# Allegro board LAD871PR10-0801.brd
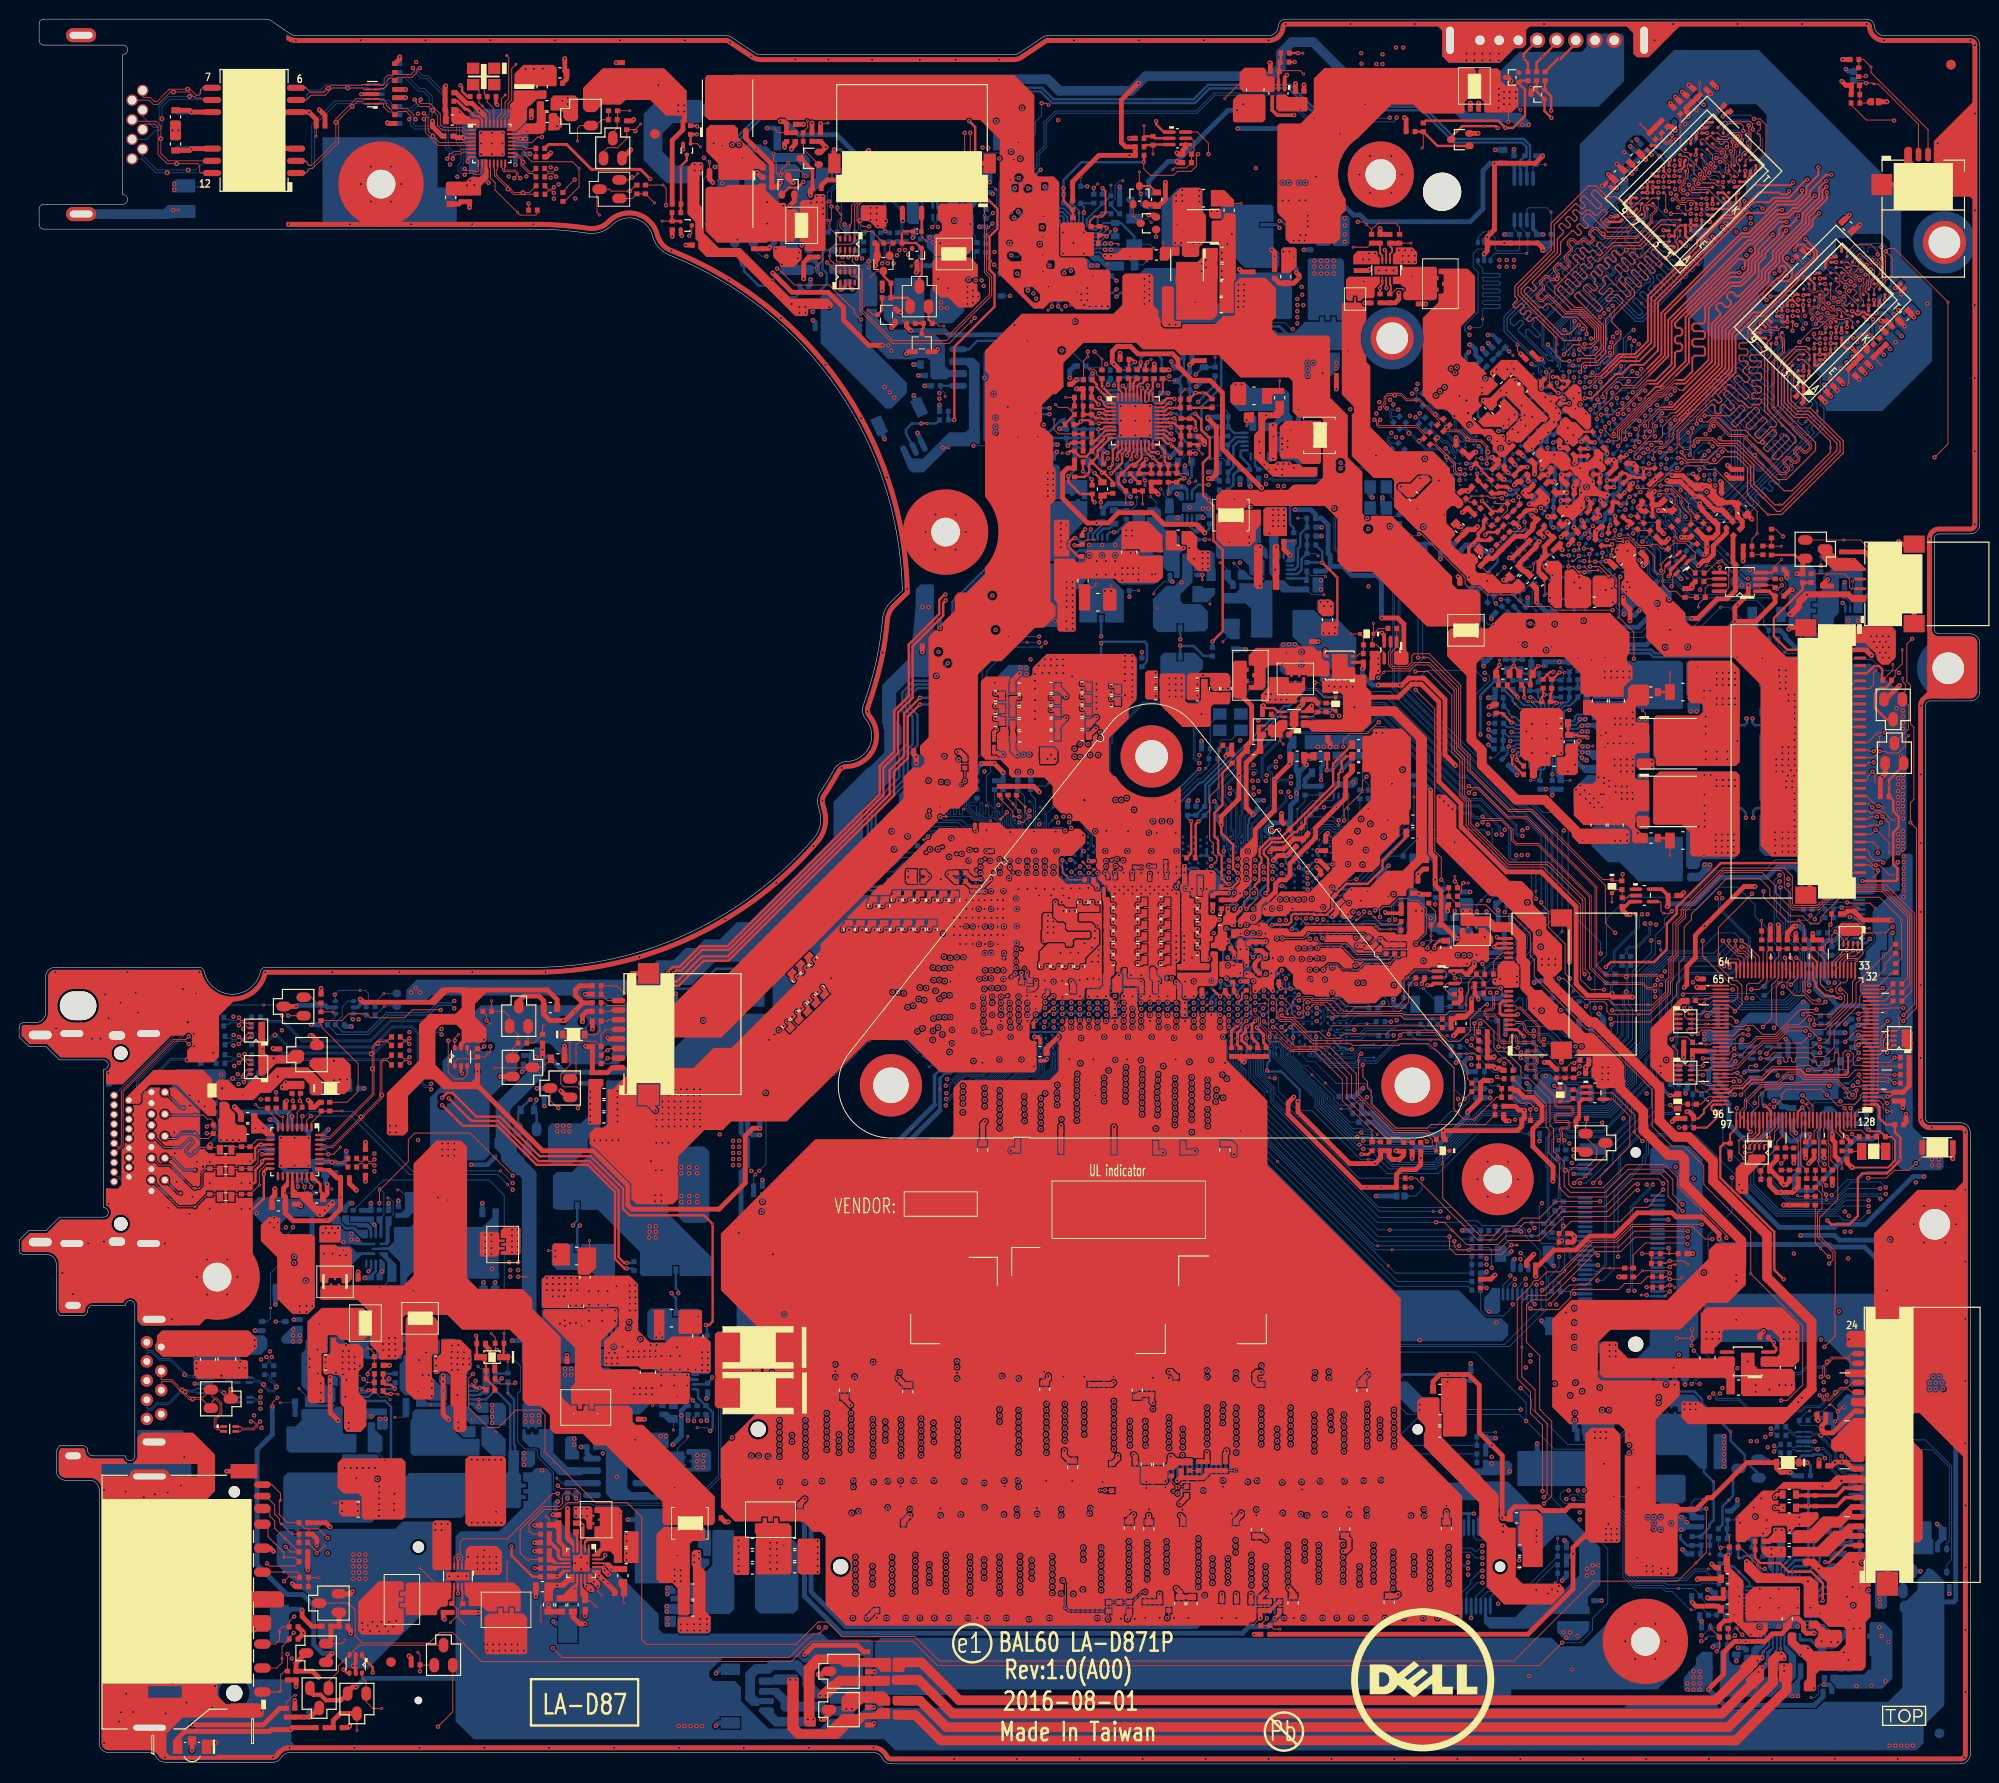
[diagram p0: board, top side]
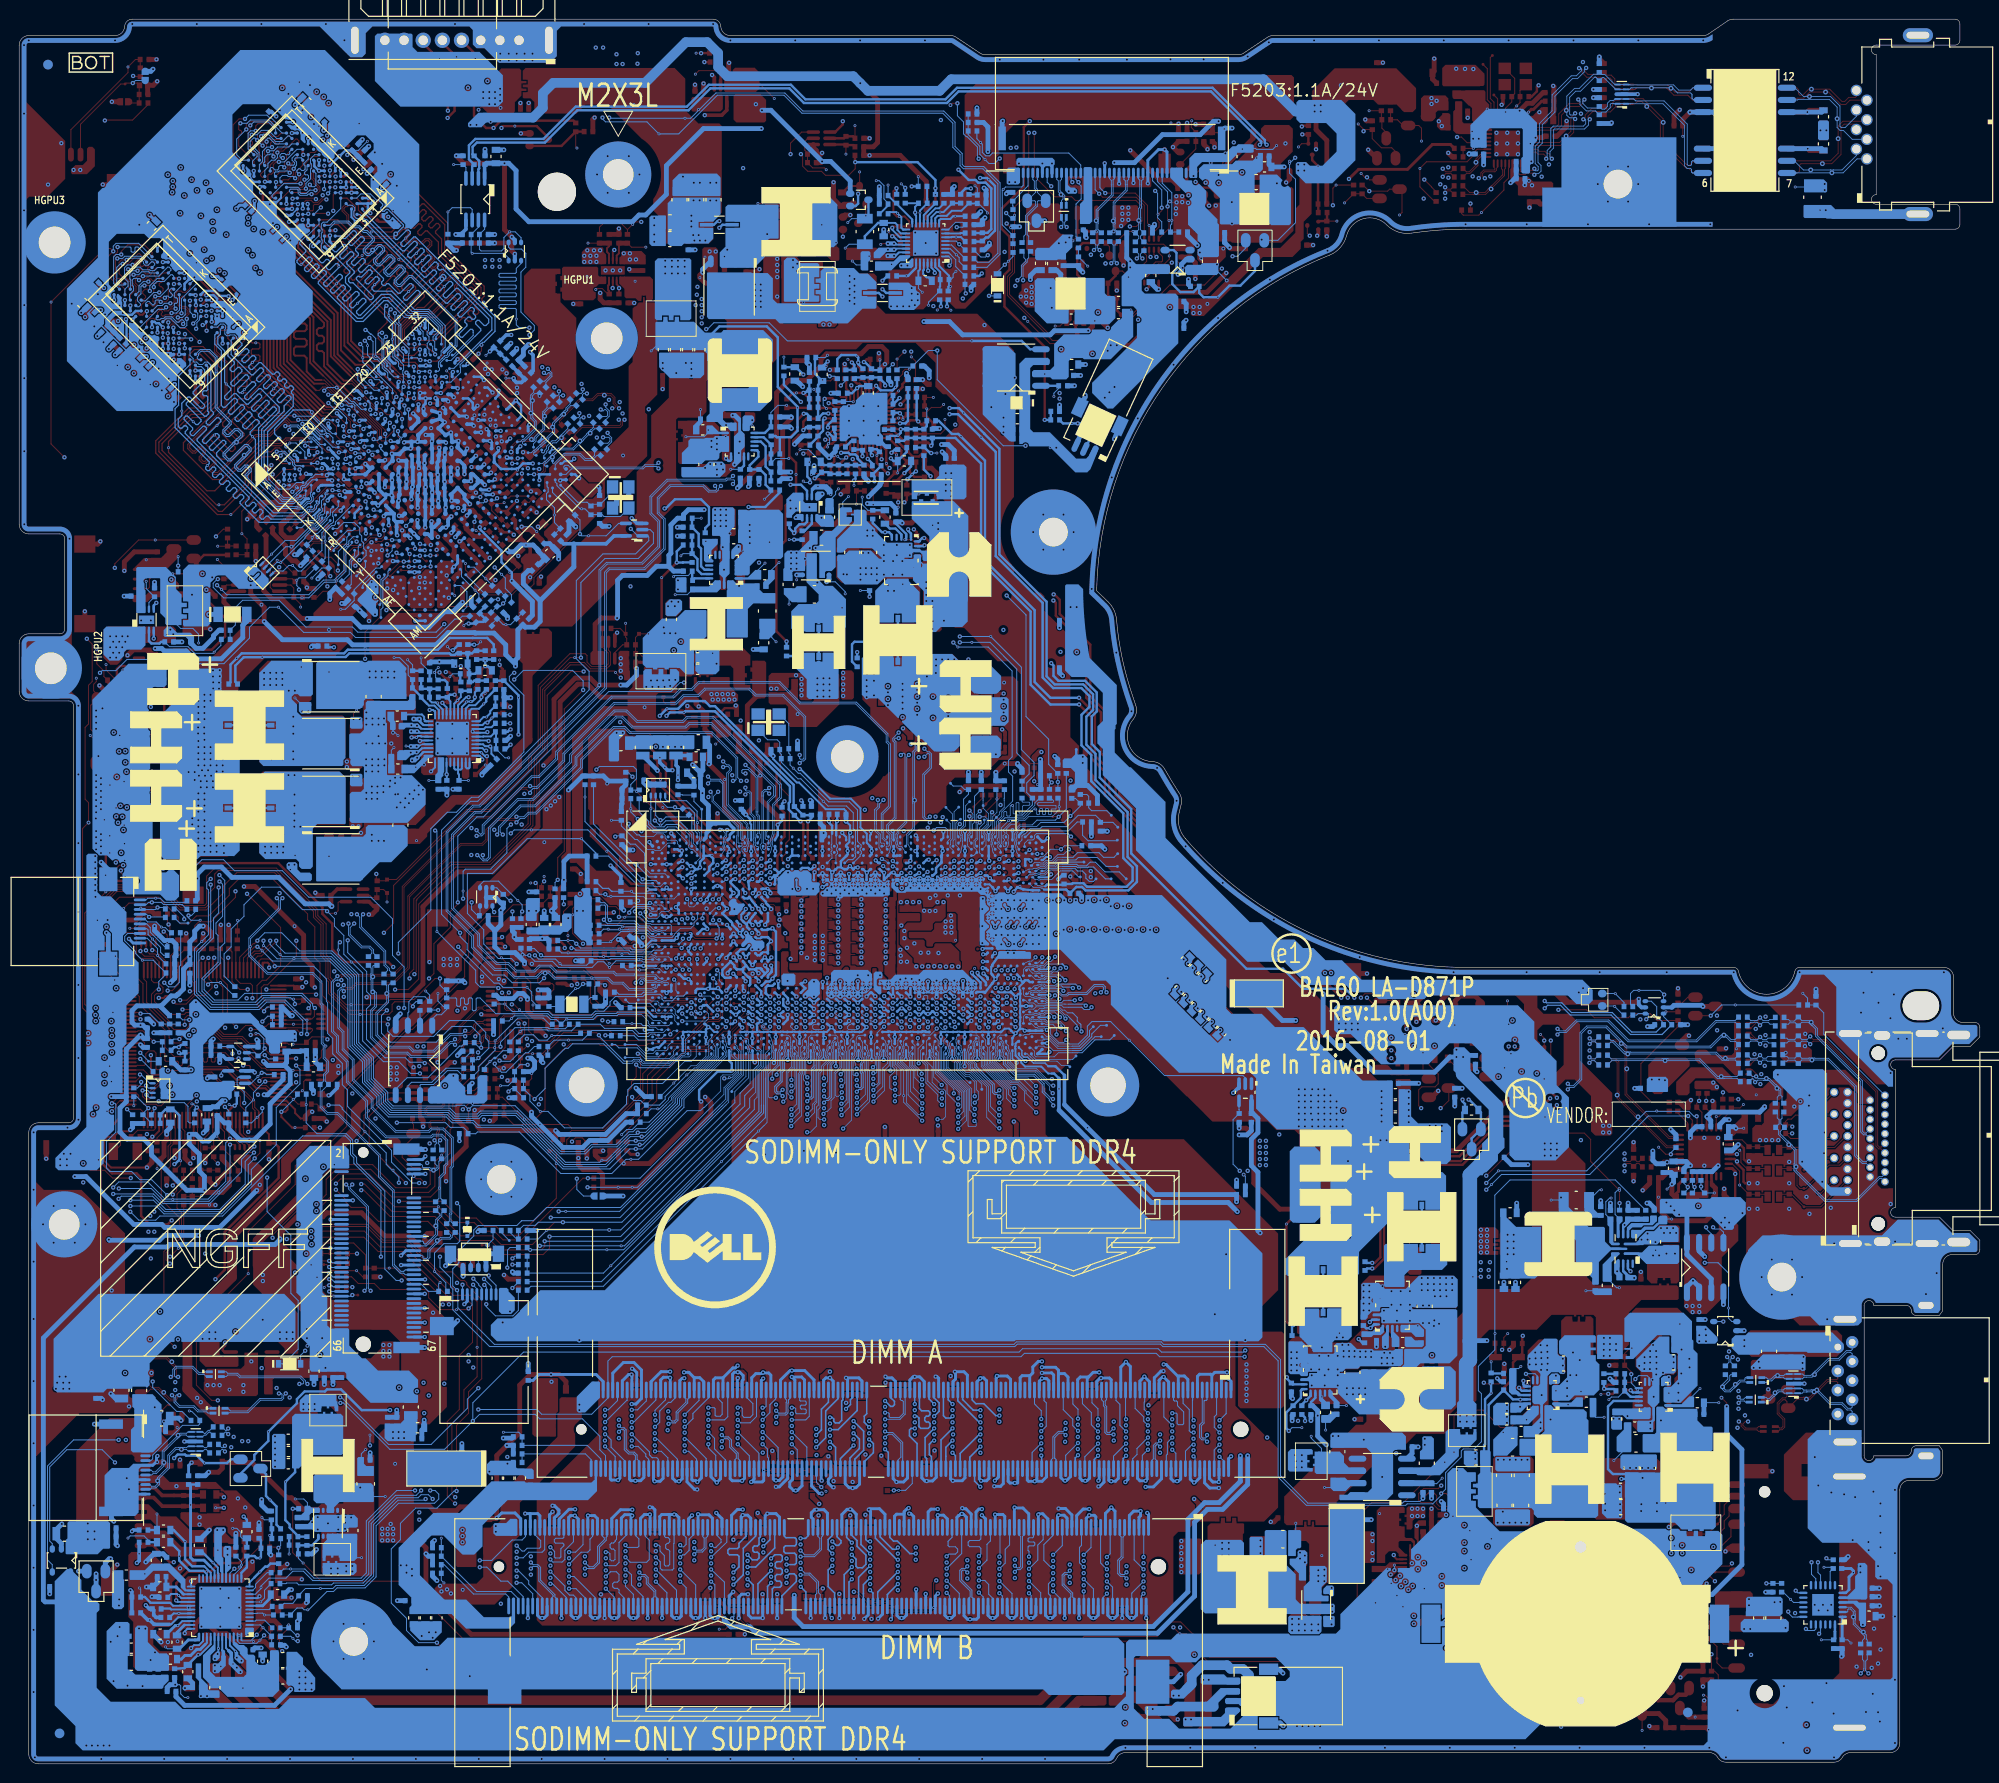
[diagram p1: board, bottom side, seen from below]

Outline 204.55 x 181.97 mm; copper layers: TOP, VCC, IN1, IN2, GND, BOTTOM. Coordinates in mm from the lower left corner of the outline.
Outline path: 0,76.82 0,75.82 1,74.82 2.8,74.82 4.2,73.42 8.8,73.42 arc(9.3,72.92) 8.8,72.42 8.8,58.02 arc(9.3,57.52) 8.8,57.02 4.2,57.02 2.8,55.62 1,55.62 0,54.62 0,53.62 arc(0.15,53.27) 0.5,53.12 2.87,53.12 arc(3.58,52.83) 3.87,52.12 3.87,47.27 4.22,46.77 6.65,46.77 arc(7,46.92) 7.15,47.27 arc(7.31,47.66) 7.7,47.82 11.07,47.82 arc(11.57,48.32) 12.07,47.82 12.07,32.12 arc(11.57,31.62) 11.07,32.12 7.7,32.12 arc(7.31,32.28) 7.15,32.67 arc(7,33.02) 6.65,33.17 4.22,33.17 3.87,32.67 3.87,30.57 arc(4.16,29.86) 4.87,29.57 7.35,29.57 arc(8.06,29.28) 8.35,28.57 8.35,2.17 arc(8.64,1.46) 9.35,1.17 13.48,1.17 arc(13.98,1.04) 14.35,0.67 arc(14.71,0.3) 15.21,0.17 26.49,0.17 arc(26.99,0.3) 27.35,0.67 arc(27.72,1.04) 28.22,1.17 89.14,1.17 arc(89.68,1.01) 90.05,0.58 arc(90.42,0.16) 90.96,0 202.55,0 arc(203.26,0.29) 203.55,1 203.55,65.86 arc(203.26,66.57) 202.55,66.86 199.38,66.86 arc(199.03,67.01) 198.88,67.36 198.88,110.36 arc(199.03,110.71) 199.38,110.86 203.55,110.86 arc(204.26,111.15) 204.55,111.86 204.55,116.86 arc(204.26,117.57) 203.55,117.86 200.3,117.86 arc(199.95,118.01) 199.8,118.36 199.8,127.78 arc(199.95,128.13) 200.3,128.28 203.55,128.28 arc(204.26,128.57) 204.55,129.28 204.55,179.26 arc(204.26,179.97) 203.55,180.26 194.55,180.26 arc(193.86,180.54) 193.55,181.21 arc(193.3,181.75) 192.75,181.97 132.15,181.97 arc(131.6,181.75) 131.35,181.21 arc(131.04,180.54) 130.35,180.26 107.35,180.26 arc(107.06,180.22) 106.8,180.09 104.3,178.43 arc(104.04,178.3) 103.75,178.26 77.35,178.26 arc(77.06,178.3) 76.8,178.43 74.3,180.09 arc(74.04,180.22) 73.75,180.26 28.86,180.26 arc(28.56,180.3) 28.29,180.43 26.31,181.8 arc(26.04,181.93) 25.74,181.97 2.58,181.97 arc(2.23,181.82) 2.08,181.47 2.08,179.77 arc(2.23,179.42) 2.58,179.27 10.81,179.27 arc(11.31,178.77) 10.81,178.27 10.81,163.67 arc(11.31,163.17) 10.81,162.67 2.58,162.67 arc(2.23,162.52) 2.08,162.17 2.08,160.57 arc(2.23,160.22) 2.58,160.07 53.65,160.07 arc(56.48,159.97) 59.3,159.65 arc(60.69,159.77) 61.87,160.51 arc(64.3,161.16) 66.07,159.38 arc(66.72,158.15) 67.86,157.35 arc(85.28,143.52) 92.14,122.36 90.96,121.22 arc(90.34,120.35) 90.06,119.31 arc(89.68,116.39) 89.04,113.52 arc(88.58,111.96) 88.07,110.41 arc(88,109.65) 88.32,108.95 arc(88.7,106.11) 86.31,104.53 arc(85.58,104.32) 85.05,103.77 arc(84.31,102.5) 83.52,101.26 arc(83.3,100.69) 83.32,100.08 83.54,99.2 arc(83.54,97.79) 82.9,96.54 arc(69.75,86.6) 53.65,83.07 25.67,83.07 arc(25.35,82.96) 25.18,82.67 arc(22.24,80.27) 19.3,82.67 arc(19.13,82.96) 18.81,83.07 3.75,83.07 arc(3.04,82.78) 2.75,82.07 2.75,78.32 arc(2.46,77.61) 1.75,77.32 0.5,77.32 arc(0.15,77.17) 0,76.82

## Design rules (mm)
constraint set DEFAULT: min track width 0.102
net group 4: nets USB_PN2_C USB_PP2_C
net group CLK_ITPXDP_: nets CLK_ITPXDP_N CLK_ITPXDP_P
net group CLK_PCIE_LAN_2: nets CLK_PCIE_LAN_N2 CLK_PCIE_LAN_P2
net group CLKTEST: nets CLKTESTA CLKTESTB
net group CPU_DP3_AUX: nets CPU_DP3_AUXN CPU_DP3_AUXP
net group DDC_CLK_HDMI: nets DDC_CLK_HDMI DDC_DATA_HDMI
net group DDC_CLK_PH1: nets DDC_CLK_PH1 DDC_DATA_PH2
net group DDR3L_CLK: nets CLKA0_C CLKA1_C
net group DDR3L_CS: nets CSA0#_0 CSA1#_0
net group DIFFPAIR41: nets SATA3_PRX_HDDTX_N0 SATA3_PRX_HDDTX_P0
net group DIFFPAIR42: nets SATA3_PTX_HDDRX_N0 SATA3_PTX_HDDRX_P0
net group DIFFPAIR43: nets EDP_AUX EDP_AUX#
net group DIFFPAIR44: nets EDP_TX0 EDP_TX0#
net group DIFFPAIR45: nets EDP_TX1 EDP_TX1#
net group DIFFPAIR46: nets USB_CAMERA_EDP USB_CAMERA_EDP#
net group DIFFPAIR47: nets USB_PN7_TPNL USB_PP7_TPNL
net group DIFFPAIR50: nets HDMI_DATA0#_R_C HDMI_DATA0_R_C
net group DIFFPAIR51: nets HDMI_DATA1#_R_C HDMI_DATA1_R_C
net group DIFFPAIR52: nets HDMI_DATA1#_R HDMI_DATA1_R
net group DIFFPAIR53: nets HDMI_DATA1 HDMI_DATA1#
net group DIFFPAIR54: nets HDMI_DATA2 HDMI_DATA2#
net group DIFFPAIR58: nets SATA_TXN2_R SATA_TXP2_R
net group DP_PCH_DPC_AUXN_U: nets PCH_DPC_AUXN_U PCH_DPC_AUXP_U
net group DP_USB3_PRX_CTX_N0_C: nets USB3_PRX_CTX_N0_C USB3_PRX_CTX_P0_C
net group EDP_AUX: nets EDP_AUX_DN EDP_AUX_DP
net group EDP_TX0: nets EDP_TX0_DN EDP_TX0_DP
net group EDP_TX1: nets EDP_TX1_DN EDP_TX1_DP
net group HDMI_CLK_R_C: nets HDMI_CLK HDMI_CLK#
net group HDMI_DATA1_R_C: nets HDMI_CRT_N1 HDMI_CRT_P1
net group HDMI_DATA2_R_C: nets HDMI_CRT_N0 HDMI_CRT_P0
net group I2C: nets I2C_SCL_TP I2C_SDA_TP
net group LAN_TXN_C_PCH_RX6: nets LAN_TXN_C_PCH_RXN6 LAN_TXP_C_PCH_RXP6
net group PCH_DPC_1_U: nets PCH_DPC_N1_U PCH_DPC_P1_U
net group PCH_DPC_AUX_U: nets PCH_DPB_AUXN PCH_DPB_AUXP
net group PCH_HDMI_CLK: nets PCH_HDMI_CLK PCH_HDMI_DATA
net group PCIE_PRX_LANTX6: nets PCIE_PRX_LANTX_N6 PCIE_PRX_LANTX_P6
net group PCIE_PRX_WLANTX_5_R: nets PCIE_PRX_WLANTX_N5_R PCIE_PRX_WLANTX_P5_R
net group PCIE_PTX_LANRX_6: nets PCIE_PTX_LANRX_N6 PCIE_PTX_LANRX_P6
net group PCIE_PTX_LANRX_6_C: nets PCIE_PTX_LANRX_N6_C PCIE_PTX_LANRX_P6_C
net group PCIE_PTX_WLANRX_5: nets PCIE_PTX_WLANRX_N5 PCIE_PTX_WLANRX_P5
net group QSA_0: nets QSA#_0 QSA_0
net group QSA_1: nets QSA#_1 QSA_1
net group QSA_2: nets QSA#_2 QSA_2
net group QSA_3: nets QSA#_3 QSA_3
net group QSA_4: nets QSA#_4 QSA_4
net group QSA_5: nets QSA#_5 QSA_5
net group QSA_6: nets QSA#_6 QSA_6
net group QSA_7: nets QSA#_7 QSA_7
net group SATA_RX0_R: nets SATA_RXN0_R SATA_RXP0_R
net group SATA_RX2_R: nets SATA_PRX_ODDTX_N1 SATA_PRX_ODDTX_P1
net group SATA_RX2R: nets SATA_RXN2_R SATA_RXP2_R
net group SATA_TX0_R: nets SATA_TXN0_R SATA_TXP0_R
net group SATA_TX2_R: nets SATA_PTX_ODDRX_N1 SATA_PTX_ODDRX_P1
net group SMBUS: nets PCH_SMBDATA SML1DATA
net group USB3.0: nets USB3_PTX_CRX_N0 USB3_PTX_CRX_P0
net group USB3_PRX_CTX_0_C: nets USB3_PRX_CTX_N0 USB3_PRX_CTX_P0
net group USB_P1_C: nets USB_PN1 USB_PP1
net group USB_P2_C: nets USB_PN2 USB_PP2
net group USB_P3: nets USB_PN3 USB_PP3
net group USB_P3_C: nets USB_PN3_C USB_PP3_C
net group USB_P6_R: nets USB_PN6_R USB_PP6_R
net group USB_P8: nets USB_PN8 USB_PP8
net group XTAL-15(18)-20(26): nets XTALIN XTALOUT
net group AUDIO: nets AUD_HP1_JACK_L AUD_HP1_JACK_L1 AUD_HP1_JACK_R AUD_HP1_JACK_R1 LINE1-L_C LINE1-L_R LINE1_L LINE1_R LINE1_VREFO_L LINE1_VREFO_R
net group CIRTICAL: nets ALL_SYS_PWRGD CBN CBP CPU_POPIRCOMP CPU_XDP_TCK0 CPVEE DDR4_DRAMRST# DMIC_CLK DMIC_CLK_R DMIC_DATA DMIC_DATA_R EC_SPI_MOSI EC_WAKE# EDP_COMP H_CATERR# H_CPU_SVIDALRT# H_DRAMRST# H_PROCHOT# H_PROCHOT#_R H_PROCHOT_EC H_THERMTRIP# H_VCCST_PWRGD INTRUDER# LAN_WAKE# LDO1_CAP LDO2_CAP LDO3_CAP PCH_DPWROK PCH_JTAG_TCK1 PCH_PCIE_WAKE# PCH_PLTRST# PCH_PLTRST#_EC PCH_RSMRST# PCH_RSMRST#_Q PCH_RTCRST# PCH_RTCX1 PCH_RTCX2 PCH_SPI_D0_0_R PCH_SPI_D0_0_R3 PCH_SPI_D0_R1 PCH_SPI_D2_0_R PCH_SPI_D2_0_R3 PCH_SPI_D2_R1 PCIE_WAKE# PECI_EC PECI_MEC1404 POK RESET_OUT# RUNPWROK SIO_PWRBTN# SIO_RCIN# SIO_SLP_A# SIO_SLP_LAN# SIO_SLP_S0# SIO_SLP_S3# SIO_SLP_S4# SIO_SLP_S5# SIO_SLP_SUS# SIO_SLP_SUS#_R SIO_SLP_WLAN# SM_RCOMP0 SM_RCOMP1 SOC_XDP_TMS SRTCRST# SYS_PWROK SYS_RESET# USBCOMP VCC_GT_SENSE VCCSENSE VCCSENSE_VCCGTUS VCCST_PWRGD VIDALERT_N VIDSCLK VIDSOUT VR_ALERT# VR_SCLK VR_SDA VSA_SEN+ VSA_SEN- VSSSENSE VSSSENSE_VCCGTUS XCLK_BIASREF XDP_HOOK0 XDP_ITP_PMODE XDP_PRSENT_PCH XDP_SPI_IO2 XDP_SPI_SI XTAL24_IN XTAL24_OUT
net group CLK-12-15: nets CLK_PEG_VGA#
net group DDR3L_CMD: nets CASA0# CASA1# CKEA0 CKEA1 ODTA0 ODTA1 RASA0# RASA1# WEA0# WEA1#
net group DDR3L_MA: nets MAA_0 MAA_1 MAA_2 MAA_3 MAA_4 MAA_5 MAA_6 MAA_7 MAA_8 MAA_9 MAA_10 MAA_11 MAA_12 MAA_13 MAA_14 MAA_15 MAA_BA_0 MAA_BA_1 MAA_BA_2
net group DDR-DQS-20-16: nets DDR_A_DQS#4
net group DDR_A-CMD-10(11)-19(20): nets DDR_A_ACT# DDR_A_ALERT# DDR_A_BG0 DDR_A_BG1 DDR_A_CKE2 DDR_A_CKE3 DDR_A_PAR
net group DDR_B-CMD-10(11)-19(20): nets DDR_B_ACT# DDR_B_ALERT# DDR_B_BG0 DDR_B_BG1 DDR_B_CKE2 DDR_B_CKE3 DDR_B_PAR
net group DQA0_D0: nets DQA0_0 DQA0_1 DQA0_2 DQA0_3 DQA0_4 DQA0_5 DQA0_6 DQA0_7
net group DQA0_D1: nets DQA0_8 DQA0_9 DQA0_10 DQA0_11 DQA0_12 DQA0_13 DQA0_14 DQA0_15
net group DQA0_D2: nets DQA0_16 DQA0_17 DQA0_18 DQA0_19 DQA0_20 DQA0_21 DQA0_22 DQA0_23
net group DQA0_D3: nets DQA0_24 DQA0_25 DQA0_26 DQA0_27 DQA0_28 DQA0_29 DQA0_30 DQA0_31
net group DQA1_D0: nets DQA1_0 DQA1_1 DQA1_2 DQA1_3 DQA1_4 DQA1_5 DQA1_6 DQA1_7
net group DQA1_D1: nets DQA1_8 DQA1_9 DQA1_10 DQA1_11 DQA1_12 DQA1_13 DQA1_14 DQA1_15
net group DQA1_D2: nets DQA1_16 DQA1_17 DQA1_18 DQA1_19 DQA1_20 DQA1_21 DQA1_22 DQA1_23
net group DQA1_D3: nets DQA1_24 DQA1_25 DQA1_26 DQA1_27 DQA1_28 DQA1_29 DQA1_30 DQA1_31
net group DQMA: nets DQMA_0 DQMA_1 DQMA_2 DQMA_3 DQMA_4 DQMA_5 DQMA_6 DQMA_7
net group DRAM_RST: nets DRAM_RST DRAM_RST_G DRAM_RST_R
net group HDA: nets HDA_CODEC_BITCLK HDA_CODEC_RST# HDA_CODEC_SDIN0 HDA_CODEC_SDOUT HDA_CODEC_SYNC HDA_RST# HDA_SDIN0 HDA_SDOUT HDA_SYNC
net group LAN: nets MDO0+ MDO0- MDO1+ MDO1-
net group LPC: nets CLK_PCI_LPC_MEC CLK_PCI_LPDEBUG LPC_LAD0 LPC_LAD1 LPC_LAD2 LPC_LAD3 LPC_LFRAME# PCI_CLK_LPC1
net group PEG: nets PEG_GTX_C_HRX_N0 PEG_GTX_C_HRX_N1 PEG_GTX_C_HRX_N2 PEG_GTX_C_HRX_N3 PEG_GTX_C_HRX_P0 PEG_GTX_C_HRX_P1 PEG_GTX_C_HRX_P2 PEG_GTX_C_HRX_P3 PEG_GTX_HRX_N0 PEG_GTX_HRX_N1 PEG_GTX_HRX_N2 PEG_GTX_HRX_N3 PEG_GTX_HRX_P0 PEG_GTX_HRX_P1 PEG_GTX_HRX_P2 PEG_GTX_HRX_P3 PEG_HTX_C_GRX_N0 PEG_HTX_C_GRX_N1 PEG_HTX_C_GRX_N2 PEG_HTX_C_GRX_N3 PEG_HTX_C_GRX_P0 PEG_HTX_C_GRX_P1 PEG_HTX_C_GRX_P2 PEG_HTX_C_GRX_P3 PEG_HTX_GRX_N0 PEG_HTX_GRX_N1 PEG_HTX_GRX_N2 PEG_HTX_GRX_N3 PEG_HTX_GRX_P0 PEG_HTX_GRX_P1 PEG_HTX_GRX_P2 PEG_HTX_GRX_P3
net group R_DDR_A-CMD: nets DDR_A_BS0 DDR_A_BS1 DDR_A_CAS# DDR_A_MA0 DDR_A_MA1 DDR_A_MA2 DDR_A_MA3 DDR_A_MA4 DDR_A_MA5 DDR_A_MA6 DDR_A_MA7 DDR_A_MA8 DDR_A_MA9 DDR_A_MA10 DDR_A_MA11 DDR_A_MA12 DDR_A_MA13 DDR_A_RAS# DDR_A_WE#
net group R_DDR_A-CTRL: nets DDR_A_CKE0 DDR_A_CKE1 DDR_A_CS#0 DDR_A_CS#1 DDR_A_ODT0 DDR_A_ODT1
net group R_DDR_A_CLK: nets DDR_A_CLK0 DDR_A_CLK1 DDR_A_CLK#0 DDR_A_CLK#1 DDR_A_DQS0 DDR_A_DQS4
net group R_DDRA-DQS0: nets DDR_A_D0 DDR_A_D1 DDR_A_D2 DDR_A_D3 DDR_A_D4 DDR_A_D5 DDR_A_D6 DDR_A_D7 DDR_A_DQS#0
net group R_DDRA-DQS1: nets DDR_A_D8 DDR_A_D9 DDR_A_D10 DDR_A_D11 DDR_A_D12 DDR_A_D13 DDR_A_D14 DDR_A_D15 DDR_A_DQS1 DDR_A_DQS#1
net group R_DDRA-DQS2: nets DDR_A_D16 DDR_A_D17 DDR_A_D18 DDR_A_D19 DDR_A_D20 DDR_A_D21 DDR_A_D22 DDR_A_D23 DDR_A_DQS2 DDR_A_DQS#2
net group R_DDRA-DQS3: nets DDR_A_D24 DDR_A_D25 DDR_A_D26 DDR_A_D27 DDR_A_D28 DDR_A_D29 DDR_A_D30 DDR_A_D31 DDR_A_DQS3 DDR_A_DQS#3
net group R_DDRA-DQS4: nets DDR_A_D32 DDR_A_D33 DDR_A_D34 DDR_A_D35 DDR_A_D36 DDR_A_D37 DDR_A_D38 DDR_A_D39
net group R_DDRA-DQS5: nets DDR_A_D40 DDR_A_D41 DDR_A_D42 DDR_A_D43 DDR_A_D44 DDR_A_D45 DDR_A_D46 DDR_A_D47 DDR_A_DQS5 DDR_A_DQS#5
net group R_DDRA-DQS6: nets DDR_A_D48 DDR_A_D49 DDR_A_D50 DDR_A_D51 DDR_A_D52 DDR_A_D53 DDR_A_D54 DDR_A_D55 DDR_A_DQS6 DDR_A_DQS#6
net group R_DDRA-DQS7: nets DDR_A_D56 DDR_A_D57 DDR_A_D58 DDR_A_D59 DDR_A_D60 DDR_A_D61 DDR_A_D62 DDR_A_D63 DDR_A_DQS7 DDR_A_DQS#7
net group R_DDRB-CLK: nets DDR_B_CLK0 DDR_B_CLK1 DDR_B_CLK#0 DDR_B_CLK#1
net group R_DDRB-CMD: nets DDR_B_BS0 DDR_B_BS1 DDR_B_CAS# DDR_B_MA0 DDR_B_MA1 DDR_B_MA2 DDR_B_MA3 DDR_B_MA4 DDR_B_MA5 DDR_B_MA6 DDR_B_MA7 DDR_B_MA8 DDR_B_MA9 DDR_B_MA10 DDR_B_MA11 DDR_B_MA12 DDR_B_MA13 DDR_B_RAS# DDR_B_WE#
net group R_DDRB-CTRL: nets DDR_B_CKE0 DDR_B_CKE1 DDR_B_CS#0 DDR_B_CS#1 DDR_B_ODT0 DDR_B_ODT1
net group R_DDRB-DQS0: nets DDR_B_D0 DDR_B_D1 DDR_B_D2 DDR_B_D3 DDR_B_D4 DDR_B_D5 DDR_B_D6 DDR_B_D7 DDR_B_DQS0 DDR_B_DQS#0
net group R_DDRB-DQS1: nets DDR_B_D8 DDR_B_D9 DDR_B_D10 DDR_B_D11 DDR_B_D12 DDR_B_D13 DDR_B_D14 DDR_B_D15 DDR_B_DQS1 DDR_B_DQS#1
net group R_DDRB-DQS2: nets DDR_B_D16 DDR_B_D17 DDR_B_D18 DDR_B_D19 DDR_B_D20 DDR_B_D21 DDR_B_D22 DDR_B_D23 DDR_B_DQS2 DDR_B_DQS#2
net group R_DDRB-DQS3: nets DDR_B_D24 DDR_B_D25 DDR_B_D26 DDR_B_D27 DDR_B_D28 DDR_B_D29 DDR_B_D30 DDR_B_D31 DDR_B_DQS3 DDR_B_DQS#3
net group R_DDRB-DQS4: nets DDR_B_D32 DDR_B_D33 DDR_B_D34 DDR_B_D35 DDR_B_D36 DDR_B_D37 DDR_B_D38 DDR_B_D39 DDR_B_DQS4 DDR_B_DQS#4
net group R_DDRB-DQS5: nets DDR_B_D40 DDR_B_D41 DDR_B_D42 DDR_B_D43 DDR_B_D44 DDR_B_D45 DDR_B_D46 DDR_B_D47 DDR_B_DQS5 DDR_B_DQS#5
net group R_DDRB-DQS6: nets DDR_B_D48 DDR_B_D49 DDR_B_D50 DDR_B_D51 DDR_B_D52 DDR_B_D53 DDR_B_D54 DDR_B_D55 DDR_B_DQS6 DDR_B_DQS#6
net group R_DDRB-DQS7: nets DDR_B_D56 DDR_B_D57 DDR_B_D58 DDR_B_D59 DDR_B_D60 DDR_B_D61 DDR_B_D62 DDR_B_D63 DDR_B_DQS7 DDR_B_DQS#7
net group SD: nets RREF SD_CLK SD_CMD SD_D0 SD_D1 SD_D2 SD_D3 SDREFG
net group SPACING-12: nets SATA_LED# SATA_ODD_DA# SATA_ODD_DA#_C SATA_ODD_PRSNT# SATA_ODD_PWRGT
net group SPACING-15: nets CFG0 CFG1 CFG2 CFG3 CFG4 CFG5 CFG6 CFG7 CFG8 CFG9 CFG10 CFG11 CFG12 CFG13 CFG14 CFG15 CFG16 CFG17 CFG18 CFG19 CFG_RCOMP CLK_SMB DAT_SMB HDA_BIT_CLK PCH_SMB_ALERT# PCH_SMBCLK PCH_SPI_CLK_R1 POL1_SDA POL2_SCL SMBCLK SMBDATA SML0_SMBCLK SML0_SMBDATA SOC_XDP_TDI SOC_XDP_TDO SOC_XDP_TRST# SUSCLK VGA_SMB_CK3 VGA_SMB_CK3_R VGA_SMB_DA3 VGA_SMB_DA3_R XDP_OBS0_R XDP_OBS1_R XDP_OBS2_R XDP_OBS3_R XDP_PRDY# XDP_PREQ# XDP_PRSENT_CPU
net group SPACING-18(15): nets CORE_VID0
net group SPI: nets EC_SPI_CLK EC_SPI_CS0# EC_SPI_MISO PCH_SPI_CLK_0_R3 PCH_SPI_CS#0_R1 PCH_SPI_CS#0_R2 PCH_SPI_D1_0_R PCH_SPI_D1_0_R3 PCH_SPI_D1_R1 PCH_SPI_D3_0_R PCH_SPI_D3_0_R3 PCH_SPI_D3_R1
net group SPK: nets AUD_SPK_L+ AUD_SPK_L+_C AUD_SPK_L- AUD_SPK_L-_C AUD_SPK_R+ AUD_SPK_R+_C AUD_SPK_R- AUD_SPK_R-_C
net group SRC: nets CLK_LAN_REQ2#_R CLK_PCIE_LAN_REQ# CLK_PCIE_WLAN_REQ# CLK_PCIE_WLAN_REQ#_R PEG_CLKREQ# PEG_CLKREQ#_G
net group SVID2: nets GPU_VID1 GPU_VID3 SVI2_SVC SVI2_SVC_R SVI2_SVD SVI2_SVD_R SVI2_SVT SVI2_SVT_R
nets with their own width: min track width 0.254; nets +1.8VALWP +MVREFDA +MVREFSA AMBER_LED_BAT AUD_PORTA_L_R_B AUD_PORTA_R_R_B BAT1_LED# BAT2_LED# BAT_AMBER BAT_WHITE BATT_WHITE_LED_R# CAP_LED CAP_LED# CAP_LED_Q CAP_LED_R# CHG_AMBER_LED_R# EN_1.8VALW FB_1.8VALW JACK_PLUG KB_BL_CTRL# KB_LED_BL_DET KB_LED_DET_C KB_LED_PWM V3D3_STB WHITE_LED_BAT
nets with their own width: min track width 0.305; nets PCH_POPIRCOMP
nets with their own width: min track width 0.381; nets SM_RCOMP2
nets with their own width: min track width 0.508; nets +1.0V_AMPHYPLL +1.0V_CLK2 +1.0V_CLK5 +1.0V_PRIM +1.0V_VCCST +1.0V_VCCSTG +1.2V_DDR +3.3V_SPI +3VALW +3VALW_EC +3VALW_PCH +3VS +5V_KB_BL +5VALW +RTC_VCC +V_DDR_REFA_R +V_DDR_REFB_R +VCC_CORE +VCC_GT ACIN_CHG EC_AGND GND GND_R1 GND_R2 GNDA RTC_PWR TP_VDD VDD_DAC_33
nets with their own width: min track width 0.762; nets +DP_VDDC +DP_VDDR +MPLL_PVDD +SPLL_PVDD +SPLL_VDDC +TSVDD +VDD_CT +VDDR3
nets with their own width: min track width 1.016; nets 5V_HDMI_CRT_S0_R MCT MCT0 MCT1 MCT2 MCT3 RING2 RING2_R SLEEVE SLEEVE_R
nets with their own width: min track width 1.27; nets +BIF_VDDC
nets with their own width: min track width 1.524; nets +PCIE_VDDC
nets with their own width: min track width 2.032; nets USB20_VCCA USB30_VCCC

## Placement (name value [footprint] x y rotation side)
AFTP2502  PAD  [TPC12]  30.54 14.35 270 top
AFTP2901  PAD  [TPC12]  89.72 5.08 90 top
AFTP2902  PAD  [TPC12]  89.72 6.73 90 top
AFTP2903  PAD  [TPC12]  89.72 8.64 90 top
AFTP2904  PAD  [TPC12]  89.72 10.29 90 top
AFTP3302  PAD  [TPC12]  27.16 13.77 0 top
AFTP3303  PAD  [TPC12]  27.62 20 0 top
AFTP3304  PAD  [TPC12]  27.36 25.02 0 top
AFTP3305  PAD  [TPC12]  27.26 27.48 0 top
AFTP3306  PAD  [TPC12]  27.62 21.54 0 top
AFTP3307  PAD  [TPC12]  27.74 23.5 0 top
AFTP3308  PAD  [TPC12]  27.22 7.58 0 top
AFTP3309  PAD  [TPC12]  27.43 10.99 0 top
AFTP3310  PAD  [TPC12]  27.36 16.56 0 top
AFTP3401  PAD  [TPC12]  23.76 44.15 0 top
AFTP5501  PAD  [TPC12]  18.35 58.1 0 top
AFTP5502  PAD  [TPC12]  18.36 60.02 0 top
AFTP5503  PAD  [TPC12]  18.35 63.83 0 top
AFTP5504  PAD  [TPC12]  15.19 71.85 0 top
AFTP5505  PAD  [TPC12]  18.35 61.93 0 top
AFTP5506  PAD  [TPC12]  17.16 68.42 0 top
AFTP5507  PAD  [TPC12]  18.36 67.66 0 top
AFTP5508  PAD  [TPC12]  18.34 65.75 0 top
AFTP5509  PAD  [TPC12]  16.85 59.51 0 top
AFTP5601  PAD  [TPC12]  188.89 37.45 0 top
AFTP6101  PAD  [TPC12]  193.5 175.21 180 top
AFTP6235  PAD  [TPC12]  94.27 105.79 180 bottom
AFTP6305  PAD  [TPC12]  189.71 23.93 0 top
AFTP6306  PAD  [TPC12]  188.4 27.99 0 top
AFTP6307  PAD  [TPC12]  189.79 21.98 0 top
AFTP6309  PAD  [TPC12]  190.38 27.64 0 top
AFTP6310  PAD  [TPC12]  187.99 24.74 0 top
AFTP6311  PAD  [TPC12]  189.34 33.63 0 top
AFTP6313  PAD  [TPC12]  190.05 29.59 0 top
C24  1U_0402_6.3V6K  [C_0402]  139.5 155.75 90 top
C26  .1U_0402_16V7K  [C_0402]  141.03 152.37 90 top
C343  330P_0402_50V7K  [C_0402]  143 152.39 90 top
C349  330P_0402_50V7K  [C_0402]  141.98 152.39 90 top
C983  1U_0402_6.3V6K  [C_0402]  143 159.52 270 top
C987  1U_0402_6.3V6K  [C_0402]  141.98 159.52 270 top
C2403  0.1U_0402_10V7K  [C_0402]  183.37 64.24 270 top
C2503  0.47U_0402_6.3V6K  [C_0402]  28.89 9.66 270 top
C2601  10U_0603_6.3V6M  [C_0603]  154.81 166.94 90 bottom
C2602  .1U_0402_16V7K  [C_0402]  155.95 166.8 90 bottom
C2603  2200P_0402_50V7K  [C_0402]  99.95 139.16 0 bottom
C2604  2.2U_0603_6.3V6K  [C_0603]  99.71 140.3 0 bottom
C2605  .1U_0402_16V7K  [C_0402]  95.47 144.81 180 bottom
C2606  470P_0603_50V8J  [C_0603]  52.32 68.2 0 bottom
C2607  2200P_0402_50V7K  [C_0402]  157.09 167.72 270 bottom
C2608  .1U_0402_16V7K  [C_0402]  156.53 159.51 180 bottom
C2609  .1U_0402_16V7K  [C_0402]  157.4 159.51 0 bottom
C2611  2.2U_0603_6.3V6K  [C_0603]  95.45 145.95 180 bottom
C2612  .1U_0402_16V7K  [C_0402]  123.67 99.85 270 bottom
C2613  100P_0402_50V8J  [C_0402]  187.25 75.13 270 bottom
C2701  4.7U_0603_6.3V6K  [C_0603]  178.94 19.3 180 top
C2702  4.7U_0603_6.3V6K  [C_0603]  190.58 18.45 180 bottom
C2703  1U_0603_16V7  [C_0603]  188.08 13.4 270 bottom
C2704  1U_0603_16V7  [C_0603]  190.56 13.53 180 bottom
C2705  2.2U_0402_6.3V6M  [C_0402]  189.96 17.37 180 bottom
C2706  10U_0603_6.3V6M  [C_0603]  184.13 8.64 270 bottom
C2707  .1U_0402_16V7K  [C_0402]  181.08 11.9 180 bottom
C2708  10U_0603_6.3V6M  [C_0603]  179.15 10 90 bottom
C2709  .1U_0402_16V7K  [C_0402]  184.91 10.19 0 bottom
C2710  .1U_0402_16V7K  [C_0402]  189.16 20.62 90 bottom
C2711  4.7U_0603_6.3V6K  [C_0603]  190.24 20.51 90 bottom
C2712  10U_0603_6.3V6M  [C_0603]  189.48 10.92 180 bottom
C2713  10U_0603_6.3V6M  [C_0603]  185.75 22.06 90 bottom
C2715  4.7U_0603_6.3V6K  [C_0603]  186.96 10.32 270 bottom
C2716  4.7U_0603_6.3V6K  [C_0603]  178.94 16.13 180 top
C2717  .1U_0402_16V7K  [C_0402]  180.7 14.26 90 top
C2718  4.7U_0603_6.3V6K  [C_0603]  178.3 17.65 180 bottom
C2719  .1U_0402_16V7K  [C_0402]  178.7 17.27 180 top
C2720  .1U_0402_16V7K  [C_0402]  178.19 23.5 180 bottom
C2723  22P_0402_50V8J  [C_0402]  175.52 14.19 0 bottom
C2901  .1U_0402_16V7K  [C_0402]  179.53 23.53 90 bottom
C2907  10U_0603_10V6M  [C_0603]  188.78 23.11 0 bottom
C2908  10U_0603_10V6M  [C_0603]  188.78 24.38 0 bottom
C3001  10P_0402_50V8J  [C_0402]  48.83 173.89 0 top
C3002  .1U_0402_16V7K  [C_0402]  52.52 172.37 0 top
C3003  .1U_0402_16V7K  [C_0402]  46.98 163.84 270 top
C3004  4.7U_0603_6.3V6K  [C_0603]  45.01 164.08 270 top
C3005  4.7U_0603_6.3V6K  [C_0603]  45.9 171.45 180 top
C3007  .1U_0402_16V7K  [C_0402]  46.09 163.84 270 top
C3008  .1U_0402_16V7K  [C_0402]  45.35 172.53 180 top
C3009  .1U_0402_16V7K  [C_0402]  54.55 170.65 0 top
C3010  4.7U_0603_6.3V6K  [C_0603]  54.37 171.73 0 top
C3011  10P_0402_50V8J  [C_0402]  47.97 173.89 180 top
C3012  4.7U_0603_6.3V6K  [C_0603]  55.7 176.37 0 top
C3013  .1U_0402_16V7K  [C_0402]  62.92 176.52 90 top
C3014  .1U_0402_16V7K  [C_0402]  53.91 165.51 0 top
C3015  1U_0402_10V6K  [C_0402]  61.48 173.33 270 top
C3016  .1U_0402_16V7K  [C_0402]  53.91 166.4 0 top
C3017  .1U_0402_16V7K  [C_0402]  47.46 165.34 0 bottom
C3018  1U_0402_10V6K  [C_0402]  51.77 168.83 270 bottom
C3019  .1U_0402_16V7K  [C_0402]  55.75 175.29 0 top
C3021  .1U_0402_16V7K  [C_0402]  45.24 169.77 180 top
C3022  .1U_0402_16V7K  [C_0402]  45.35 174.31 180 top
C3023  .1U_0402_16V7K  [C_0402]  52.66 168.83 270 bottom
C3024  .1U_0402_16V7K  [C_0402]  47.46 167.13 0 bottom
C3025  .1U_0402_16V7K  [C_0402]  47.46 166.23 0 bottom
C3101  100P_1206_2KV8J  [C_1206]  17.46 164.72 270 bottom
C3106  0.01U_0402_50V7K  [C_0402]  30.99 170.85 0 top
C3201  1U_0402_10V6K  [C_0402]  15.25 12.02 90 bottom
C3202  .1U_0402_16V7K  [C_0402]  12.16 18.32 180 bottom
C3203  4.7U_0603_6.3V6K  [C_0603]  12.27 15.4 180 bottom
C3204  0.01U_0402_50V7K  [C_0402]  12.16 17.43 180 bottom
C3205  .1U_0402_16V7K  [C_0402]  12.16 16.48 180 bottom
C3206  1U_0402_10V6K  [C_0402]  14.41 20.37 90 bottom
C3301  .1U_0402_16V7K  [C_0402]  24.14 15.66 270 bottom
C3302  4.7U_0603_6.3V6K  [C_0603]  23.06 15.91 270 bottom
C3303  10U_0805_10V6K  [C_0805]  21.54 16.06 270 bottom
C3403  .1U_0402_16V7K  [C_0402]  26.54 41.51 270 bottom
C3404  .1U_0402_16V7K  [C_0402]  25.6 41.51 270 bottom
C3504  .1U_0402_16V7K  [C_0402]  200.45 18.48 0 bottom
C3507  .1U_0402_16V7K  [C_0402]  19.7 43.35 270 bottom
C3508  1U_0402_10V6K  [C_0402]  20.65 43.35 270 bottom
C3510  1U_0402_10V6K  [C_0402]  29.29 45.42 90 bottom
C3512  22UF_0805_6.3V6M  [C_0805]  21.99 43.87 270 bottom
C3513  22UF_0805_6.3V6M  [C_0805]  19.7 43.05 270 top
C3515  22UF_0805_6.3V6M  [C_0805]  198.98 24 0 bottom
C3517  .1U_0402_16V7K  [C_0402]  195.35 23.72 180 bottom
C3518  1U_0402_10V6K  [C_0402]  195.35 24.6 180 bottom
C5201  .1U_0402_16V7K  [C_0402]  79.7 158.75 180 bottom
C5202  1000P_0402_50V7K  [C_0402]  75.06 167.7 180 bottom
C5203  .1U_0402_16V7K  [C_0402]  89.88 158.78 90 bottom
C5204  4.7U_0603_6.3V6K  [C_0603]  86.49 155.94 270 bottom
C5205  0.1U_0603_50V7K  [C_0603]  73.91 166.56 0 bottom
C5206  1U_0402_10V6K  [C_0402]  78.78 159.7 0 bottom
C5207  4.7U_0603_6.3V6K  [C_0603]  96.72 157.19 270 bottom
C5208  10P_0402_50V8J  [C_0402]  100.87 159.4 90 bottom
C5209  .1U_0402_16V7K  [C_0402]  88.1 157.83 90 bottom
C5210  .1U_0402_16V7K  [C_0402]  90.77 158.78 90 bottom
C5211  .1U_0402_16V7K  [C_0402]  91.66 158.78 90 bottom
C5212  .1U_0402_16V7K  [C_0402]  87.21 157.83 90 bottom
C5213  .1U_0402_16V7K  [C_0402]  92.55 158.78 90 bottom
C5214  10P_0402_50V8J  [C_0402]  100.89 162.99 90 bottom
C5224  1U_0603_16V7  [C_0603]  189.99 73.28 180 bottom
C5225  10P_0402_50V8J  [C_0402]  191.06 63.93 90 top
C5226  10P_0402_50V8J  [C_0402]  193.78 65.4 0 top
C5401  .1U_0402_16V7K  [C_0402]  20.26 68.74 0 top
C5402  .1U_0402_16V7K  [C_0402]  25.17 77.88 180 bottom
C5403  .1U_0402_16V7K  [C_0402]  25.17 76.99 180 bottom
C5404  .1U_0402_16V7K  [C_0402]  25.17 75.91 180 bottom
C5405  .1U_0402_16V7K  [C_0402]  25.17 75.02 180 bottom
C5406  .1U_0402_16V7K  [C_0402]  25.17 73.06 180 bottom
C5407  .1U_0402_16V7K  [C_0402]  24.98 72.04 180 bottom
C5408  .1U_0402_16V7K  [C_0402]  24.98 71.15 180 bottom
C5409  .1U_0402_16V7K  [C_0402]  25.17 73.94 180 bottom
C5501  .1U_0402_16V7K  [C_0402]  33.53 61.12 0 top
C5502  10U_0603_6.3V6M  [C_0603]  26.24 65.37 270 bottom
C5503  .1U_0402_16V7K  [C_0402]  27.59 59.34 180 top
C5504  2.2U_0603_10V7K  [C_0603]  27.76 58.2 180 top
C5506  10P_0402_50V  [C_0402]  23.19 59.42 270 top
C5507  18P_0402_50V8J  [C_0402]  20.26 66.64 0 top
C5509  10P_0402_50V  [C_0402]  23.19 64.37 270 top
C5510  10P_0402_50V  [C_0402]  19.89 62.08 270 top
C5511  100P_0402_50V8J  [C_0402]  29.53 68.48 0 top
C5512  10P_0402_50V  [C_0402]  23.19 62.08 270 top
C5513  18P_0402_50V8J  [C_0402]  20.26 65.75 0 top
C5514  10P_0402_50V  [C_0402]  19.89 59.42 270 top
C5516  100P_0402_50V8J  [C_0402]  28.67 68.48 180 top
C5517  .1U_0402_16V7K  [C_0402]  33.03 61.68 90 bottom
C5518  10P_0402_50V  [C_0402]  19.89 64.3 270 top
C5519  0.01U_0402_16V7K  [C_0402]  20.26 67.85 0 top
C5520  .1U_0402_16V7K  [C_0402]  28.07 66.45 0 bottom
C5521  10U_0603_6.3V6M  [C_0603]  23.13 66.2 0 top
C5522  .1U_0402_16V7K  [C_0402]  28.72 59.29 270 top
C5523  10U_0603_6.3V6M  [C_0603]  31.95 62.83 270 bottom
C5524  .1U_0402_16V7K  [C_0402]  26.23 66.45 0 bottom
C5525  .1U_0402_16V7K  [C_0402]  39.76 75.82 180 top
C5526  .1U_0402_16V7K  [C_0402]  39.76 73.91 180 top
C5527  .1U_0402_16V7K  [C_0402]  35.21 62.26 180 top
C5528  .1U_0402_16V7K  [C_0402]  35.21 63.15 180 top
C5529  .1U_0402_16V7K  [C_0402]  39.76 72.9 180 top
C5530  .1U_0402_16V7K  [C_0402]  39.76 74.93 180 top
C5601  10U_0805_10V6K  [C_0805]  193.88 39.81 270 bottom
C5602  0.01U_0402_50V7K  [C_0402]  184.67 32.43 180 bottom
C5603  0.01U_0402_50V7K  [C_0402]  184.67 33.32 180 bottom
C5604  .1U_0402_16V7K  [C_0402]  196.55 39.03 270 bottom
C5605  10U_0805_10V6K  [C_0805]  190.54 36.02 180 bottom
C5606  .1U_0402_16V7K  [C_0402]  190.19 34.67 180 bottom
C5607  0.01U_0402_50V7K  [C_0402]  168.11 83.28 90 bottom
C5608  0.01U_0402_50V7K  [C_0402]  167.22 83.28 90 bottom
C5609  10U_0805_10V6K  [C_0805]  184.52 42.19 270 top
C5610  10U_0805_10V6K  [C_0805]  178.53 39.24 0 top
C5611  0.01U_0402_50V7K  [C_0402]  165.54 81.46 90 bottom
C5612  0.01U_0402_50V7K  [C_0402]  166.49 81.46 90 bottom
C5615  0.01U_0402_50V7K  [C_0402]  183.39 35.15 0 bottom
C5616  0.01U_0402_50V7K  [C_0402]  183.39 34.26 0 bottom
C5801  .1U_0402_16V7K  [C_0402]  165.16 35.23 90 bottom
C5802  .1U_0402_16V7K  [C_0402]  166.11 35.23 90 bottom
C5803  .1U_0402_16V7K  [C_0402]  170.92 41.2 270 bottom
C5804  .1U_0402_16V7K  [C_0402]  171.81 41.2 270 bottom
C5805  10U_0603_6.3V6M  [C_0603]  163.7 35.05 180 bottom
C5806  10U_0603_6.3V6M  [C_0603]  173.79 41.66 270 bottom
C6201  .1U_0402_16V7K  [C_0402]  60.64 72.09 270 top
C6202  .1U_0402_16V7K  [C_0402]  189.05 121.94 90 top
C6204  .1U_0402_16V7K  [C_0402]  52.97 75.18 180 top
C6205  .1U_0402_16V7K  [C_0402]  53.93 163.7 0 top
C6206  .1U_0402_16V7K  [C_0402]  53.93 164.59 0 top
C6209  330P_0402_50V7K  [C_0402]  190.43 122.63 270 bottom
C6211  0.1U_0402_16V7K  [C_0402]  188.45 117.02 0 bottom
C6213  4.7U_0603_6.3V6K  [C_0603]  184.46 14.41 90 top
C6214  .1U_0402_16V7K  [C_0402]  178.7 18.16 180 top
C6215  .1U_0402_16V7K  [C_0402]  186.16 14.48 0 top
C6216  .1U_0402_16V7K  [C_0402]  145.98 153.19 270 top
C6217  .1U_0402_16V7K  [C_0402]  191.95 121.79 0 bottom
CARD1  T-SOL_156-1001902605  [T-SOL_156-1001902605_11P]  25.37 9.99 270 top
CC4  12P_0402_50V8J  [C_0402]  152.84 69.47 180 bottom
CC5  12P_0402_50V8J  [C_0402]  151.95 72.2 0 bottom
CC8  33P_0402_50V8J  [C_0402]  158.24 74.33 180 bottom
CC9  0.1U_0402_25V6  [C_0402]  158.49 70.13 180 bottom
CC10  0.1U_0402_10V7K  [C_0402]  162.85 73.41 0 top
CC21  15P_0402_50V8J  [C_0402]  124.26 105.88 180 bottom
CC22  15P_0402_50V8J  [C_0402]  125.2 105.79 0 bottom
CC23  6.8P_0402_50V8C  [C_0402]  144.48 79.93 270 bottom
CC24  1U_0402_6.3V6K  [C_0402]  141.14 64.87 270 top
CC25  1U_0402_6.3V6K  [C_0402]  145.33 64.81 270 top
CC26  6.8P_0402_50V8C  [C_0402]  149.28 78.99 90 bottom
CC27  22P_0402_50V8J  [C_0402]  152.46 49.64 90 top
CC58  0.1U_0402_16V7K  [C_0402]  76 67.83 270 bottom
CC174  10U_0402_6.3V6M  [C_0402]  113.31 64.73 0 top
CC175  10U_0402_6.3V6M  [C_0402]  117.65 63.82 0 top
CC176  10U_0402_6.3V6M  [C_0402]  120.5 64.71 0 top
CC177  10U_0402_6.3V6M  [C_0402]  105.08 64.03 180 top
CC178  10U_0402_6.3V6M  [C_0402]  105.08 64.92 180 top
CC179  10U_0402_6.3V6M  [C_0402]  113.31 63.84 0 top
CC180  10U_0402_6.3V6M  [C_0402]  109.55 85.55 0 top
CC181  1U_0402_6.3V6K  [C_0402]  122.86 82.25 90 top
CC182  1U_0402_6.3V6K  [C_0402]  114.3 81.61 180 top
CC183  1U_0402_6.3V6K  [C_0402]  109.62 86.44 90 top
CC184  10U_0402_6.3V6M  [C_0402]  110.51 86.46 90 top
CC185  1U_0402_6.3V6K  [C_0402]  123.75 82.25 90 top
CC186  1U_0402_6.3V6K  [C_0402]  121.08 82.25 90 top
CC187  10U_0402_6.3V6M  [C_0402]  108.7 87.33 90 top
CC194  1U_0402_6.3V6K  [C_0402]  115.5 80.66 90 top
CC195  1U_0402_6.3V6K  [C_0402]  129.21 99.57 90 bottom
CC199  1U_0402_6.3V6K  [C_0402]  124.96 98.86 90 bottom
CC202  1U_0402_6.3V6K  [C_0402]  124.53 90.53 270 top
CC203  1U_0402_6.3V6K  [C_0402]  144.44 90.8 0 top
CC204  1U_0402_6.3V6K  [C_0402]  142.46 80.48 0 bottom
CC205  1U_0402_6.3V6K  [C_0402]  127.36 85.6 0 top
CC206  1U_0402_6.3V6K  [C_0402]  127.37 84.21 270 top
CC207  1U_0402_6.3V6K  [C_0402]  145.09 88.72 180 top
CC208  1U_0402_6.3V6K  [C_0402]  145.09 89.61 180 top
CC209  1U_0402_6.3V6K  [C_0402]  126.69 86.49 180 top
CC210  47U_0805_6.3V6M  [C_0805]  142.62 106.45 180 bottom
CC211  1U_0402_6.3V6K  [C_0402]  137.23 96.27 180 top
CC212  1U_0402_6.3V6K  [C_0402]  129.15 84.82 90 top
CC213  1U_0402_6.3V6K  [C_0402]  126.6 81.55 90 top
CC214  0.1U_0402_10V7K  [C_0402]  137.67 69.6 0 bottom
CC215  0.5P_0402_50V8  [C_0402]  128.02 81.61 270 top
CC216  1U_0402_6.3V6K  [C_0402]  136.52 107.96 270 top
CC217  1U_0402_6.3V6K  [C_0402]  126.42 85.05 180 top
CC218  1U_0402_6.3V6K  [C_0402]  132.52 97.47 135 top
CC219  47U_0805_6.3V6M  [C_0805]  139.49 105.16 90 bottom
CC220  47U_0805_6.3V6M  [C_0805]  136.01 105.17 90 bottom
CC221  47U_0805_6.3V6M  [C_0805]  132.85 106.55 0 bottom
CC223  0.1U_0402_10V7K  [C_0402]  129.39 81.55 90 top
CC224  1U_0402_6.3V6K  [C_0402]  130.52 81.56 0 top
CC225  0.5P_0402_50V8  [C_0402]  137.27 90.59 315 top
CC226  47U_0805_6.3V6M  [C_0805]  137.72 105.17 90 bottom
CC248  10U_0402_6.3V6M  [C_0402]  124.63 84.47 90 top
CC249  10U_0402_6.3V6M  [C_0402]  124.59 83.36 0 top
CC250  1U_0402_6.3V6K  [C_0402]  124.59 82.47 0 top
CC251  1U_0402_6.3V6K  [C_0402]  114.3 80.72 180 top
CC252  1U_0402_6.3V6K  [C_0402]  121.97 82.25 90 top
CC253  1U_0402_6.3V6K  [C_0402]  122.48 80.7 0 top
CC255  1U_0402_6.3V6K  [C_0402]  116.38 80.66 90 top
CC256  1U_0402_6.3V6K  [C_0402]  117.65 64.71 0 top
CC257  1U_0402_6.3V6K  [C_0402]  109.59 64.8 180 top
CC264  1U_0402_6.3V6K  [C_0402]  133.78 97.67 315 top
CC265  1U_0402_6.3V6K  [C_0402]  129.85 83.34 180 top
CC266  1U_0402_6.3V6K  [C_0402]  160.64 55.31 0 top
CC270  0.1U_0402_10V7K  [C_0402]  126.74 80.67 180 top
CC271  1U_0402_6.3V6K  [C_0402]  150.55 90.03 90 bottom
CC272  1U_0402_6.3V6K  [C_0402]  140.83 86.3 315 bottom
CC273  1U_0402_6.3V6K  [C_0402]  145.01 92.07 0 top
CC279  22U_0603_6.3V6M  [C_0603]  149.77 86.83 90 bottom
CC280  22U_0603_6.3V6M  [C_0603]  148.57 86.83 90 bottom
CC281  0.1U_0402_10V7K  [C_0402]  137.23 95.25 180 top
CC288  1U_0402_6.3V6K  [C_0402]  108.68 86.1 270 top
CC289  1U_0402_6.3V6K  [C_0402]  111.4 86.44 90 top
CC290  1U_0402_6.3V6K  [C_0402]  93.37 92.1 0 top
CC291  1U_0402_6.3V6K  [C_0402]  93.37 92.99 0 top
CC292  1U_0402_6.3V6K  [C_0402]  107.79 86.12 270 top
CC293  22U_0603_6.3V6M  [C_0603]  138.3 25.21 270 top
CC294  22U_0603_6.3V6M  [C_0603]  125.79 63.31 90 top
CC295  22U_0603_6.3V6M  [C_0603]  100.51 63.31 90 top
CC296  10U_0402_6.3V6M  [C_0402]  109.59 63.91 180 top
CC297  0.1U_0402_10V7K  [C_0402]  120.5 63.82 0 top
CC298  0.1U_0402_16V7K  [C_0402]  164.34 72.01 180 top
CC299  0.1U_0402_16V7K  [C_0402]  172.03 90.56 0 top
CC1101  100P_0402_50V8J  [C_0402]  93.61 98.23 180 bottom
CC1103  1U_0402_6.3V6K  [C_0402]  167.24 90.34 270 top
CC1801  8.2P_0402_50V8D  [C_0402]  146.81 94.25 270 top
CD1  1U_0402_6.3V6K~D  [C_0402]  116.45 30.47 90 top
CD2  1U_0402_6.3V6K~D  [C_0402]  111.75 38.66 90 top
CD3  1U_0402_6.3V6K~D  [C_0402]  147.75 37.91 0 top
CD4  1U_0402_6.3V6K~D  [C_0402]  147.75 36.96 0 top
CD5  10U_0603_6.3V6M~D  [C_0603]  109.91 30.23 90 top
CD6  10U_0603_6.3V6M~D  [C_0603]  106.99 38.35 90 top
CD7  10U_0603_6.3V6M~D  [C_0603]  92.7 38.1 90 top
CD8  10U_0603_6.3V6M~D  [C_0603]  86.1 39.69 270 top
CD9  10U_0603_6.3V6M~D  [C_0603]  147.5 35.88 0 top
CD10  10U_0603_6.3V6M~D  [C_0603]  147.5 34.61 0 top
CD11  330U_D3_2.5VY_R6M  [C_D3]  80.28 38.67 180 top
CD12  1U_0402_6.3V6K~D  [C_0402]  151.19 29.07 90 bottom
CD13  10U_0603_6.3V6M~D  [C_0603]  152.27 29.08 90 bottom
CD14  10U_0603_6.3V6M~D  [C_0603]  153.47 29.08 90 bottom
CD15  10U_0603_6.3V6M~D  [C_0603]  154.68 29.08 90 bottom
CD16  0.1U_0402_16V7K~D  [C_0402]  151.44 39.99 90 bottom
CD17  2.2U_0603_6.3V6K~D  [C_0603]  147.5 39.05 0 top
CD18  0.1U_0402_16V7K~D  [C_0402]  121.21 30.59 90 top
CD19  1U_0402_6.3V6K~D  [C_0402]  126.93 24.24 90 top
CD20  1U_0402_6.3V6K~D  [C_0402]  121.41 24.18 90 top
CD21  1U_0402_6.3V6K~D  [C_0402]  92.26 24.12 90 top
CD22  1U_0402_6.3V6K~D  [C_0402]  117.47 15.99 90 top
CD23  10U_0603_6.3V6M~D  [C_0603]  115.82 23.88 90 top
CD24  10U_0603_6.3V6M~D  [C_0603]  117.85 23.8 90 top
CD25  10U_0603_6.3V6M~D  [C_0603]  148.9 23.81 90 top
CD26  10U_0603_6.3V6M~D  [C_0603]  129.09 25.15 270 top
CD27  10U_0603_6.3V6M~D  [C_0603]  155.82 21.02 0 top
CD28  10U_0603_6.3V6M~D  [C_0603]  155.82 22.29 0 top
CD29  0.1U_0402_16V7K~D  [C_0402]  129.47 15.99 90 top
CD30  1U_0402_6.3V6K~D  [C_0402]  155.81 23.37 0 top
CD31  1U_0402_6.3V6K~D  [C_0402]  155.81 24.32 0 top
CD32  1U_0402_6.3V6K~D  [C_0402]  163.37 17.02 0 bottom
CD33  220U_D7_2VM_R6M  [C_EEFSS0D221R]  80.28 43.43 180 top
CD34  0.1U_0402_16V7K~D  [C_0402]  163.46 33.91 180 bottom
CD35  2.2U_0603_6.3V6K~D  [C_0603]  155.5 25.65 0 top
CD69  0.1U_0402_16V7K~D  [C_0402]  115.82 16.84 270 top
CD70  10U_0603_6.3V6M~D  [C_0603]  118.87 31.94 270 top
CD71  10U_0603_6.3V6M~D  [C_0603]  140.07 38.23 90 top
CD72  10U_0603_6.3V6M~D  [C_0603]  117.6 31.94 270 top
CD73  10U_0603_6.3V6M~D  [C_0603]  116.64 39.69 270 top
CD74  1U_0402_6.3V6K~D  [C_0402]  129.66 38.66 90 top
CD75  1U_0402_6.3V6K~D  [C_0402]  120.71 39.42 90 top
CD76  1U_0402_6.3V6K~D  [C_0402]  118.17 39.45 270 top
CD77  1U_0402_6.3V6K~D  [C_0402]  113.34 38.66 90 top
CD78  1U_0402_6.3V6K~D  [C_0402]  81.46 26.02 90 top
CD79  1U_0402_6.3V6K~D  [C_0402]  113.98 30.4 90 top
CD80  1U_0402_6.3V6K~D  [C_0402]  89.46 16.9 270 top
CD81  1U_0402_6.3V6K~D  [C_0402]  126.99 16.05 90 top
CD82  1U_0402_6.3V6K~D  [C_0402]  125.47 16.12 90 top
CD83  1U_0402_6.3V6K~D  [C_0402]  118.99 15.99 90 top
CD84  10U_0603_6.3V6M~D  [C_0603]  142.93 16.13 90 top
CD85  10U_0603_6.3V6M~D  [C_0603]  132.9 16.07 90 top
CD86  10U_0603_6.3V6M~D  [C_0603]  122.36 16 90 top
CD87  10U_0603_6.3V6M~D  [C_0603]  121.09 16 90 top
CD88  10U_0603_6.3V6M~D  [C_0603]  160.97 15.94 270 bottom
CD89  10U_0603_6.3V6M~D  [C_0603]  162.17 15.94 270 bottom
CD90  10U_0603_6.3V6M~D  [C_0603]  163.38 15.94 270 bottom
CE8  0.047U_0402_16V4Z  [C_0402]  187.13 85.01 90 top
CE12  1U_0402_6.3V6K  [C_0402]  191.64 67.7 270 bottom
CE62  0.1U_0402_10V7K  [C_0402]  183.89 67.61 90 bottom
CE63  1000P_0402_50V7K  [C_0402]  173.65 74.36 0 bottom
CE64  1000P_0402_50V7K  [C_0402]  195.64 69.14 90 top
CE65  0.1U_0402_25V6  [C_0402]  186.75 83.39 270 bottom
CE66  0.1U_0402_25V6  [C_0402]  191.19 75.64 270 bottom
CE67  0.1U_0402_25V6  [C_0402]  196.53 70.05 270 top
CE68  0.1U_0402_25V6  [C_0402]  175.7 80.95 90 top
CE69  0.1U_0402_25V6  [C_0402]  174.57 74.36 180 top
CE70  0.1U_0402_10V7K  [C_0402]  183.83 61.93 270 top
CE71  0.1U_0402_25V6  [C_0402]  183.57 85.01 90 top
CE72  0.047U_0402_16V4Z  [C_0402]  182.68 85.01 90 top
CE73  0.1U_0402_10V7K  [C_0402]  189.78 63.06 0 top
CE74  0.1U_0402_10V7K  [C_0402]  178.12 78.93 180 bottom
CE75  220P_0402_50V8J  [C_0402]  188.02 85.01 90 top
CE76  100P_0402_50V8J  [C_0402]  178.49 64.72 270 top
CE77  0.1U_0402_25V6  [C_0402]  174.69 67.31 180 top
CE78  0.1U_0402_10V7K  [C_0402]  181.78 86.87 0 top
CE79  0.1U_0402_25V6  [C_0402]  191.19 76.76 90 bottom
CE81  0.1U_0402_25V6  [C_0402]  186.37 64.85 270 top
CE82  1000P_0402_50V7K  [C_0402]  178.12 77.98 180 bottom
CE84  100P_0402_50V8J  [C_0402]  192.72 66.79 90 bottom
CE85  0.1U_0402_10V7K  [C_0402]  183.62 73.91 0 bottom
CE86  47P_0402_50V8J  [C_0402]  183.62 74.87 0 bottom
CE87  2200P_0402_25V7K  [C_0402]  185.15 64.24 270 top
CE88  2200P_0402_25V7K  [C_0402]  186.49 59.19 270 top
CE89  10U_0603_6.3V6M  [C_0603]  174.55 72.71 180 bottom
CE91  0.1U_0402_25V6  [C_0402]  189.73 77.17 270 bottom
CH100  0.022U_0402_25V7K  [C_0402]  77.54 59.37 180 bottom
CH101  0.022U_0402_25V7K  [C_0402]  123.06 31.51 270 top
CMOS1  SHORT PADS~D  [SHORTPADS]  144.1 59.22 180 bottom
CN6301  CVILU_CF31241D0R4-10-NH  [CVILU_CF31241D0R4-10-NH_24P]  191.85 21.77 90 top
CV1  0.22U_0402_16V7K  [C_0402]  143.24 137.1 315 bottom
CV2  0.22U_0402_16V7K  [C_0402]  143.88 137.74 315 bottom
CV3  0.22U_0402_16V7K  [C_0402]  143.37 139.9 315 bottom
CV4  0.22U_0402_16V7K  [C_0402]  144.01 140.53 315 bottom
CV5  0.22U_0402_16V7K  [C_0402]  147.18 138.88 315 top
CV6  0.22U_0402_16V7K  [C_0402]  146.55 138.25 315 top
CV7  0.22U_0402_16V7K  [C_0402]  147.94 139.64 315 top
CV8  0.22U_0402_16V7K  [C_0402]  148.58 140.28 315 top
CV9  1000P_0402_50V7K  [C_0402]  183.19 122.68 90 top
CV10  0.1U_0402_16V4Z  [C_0402]  183.19 121.79 0 top
CV11  0.082U_0402_16V  [C_0402]  155.5 128.52 135 top
CV15  0.68U_0402_10V  [C_0402]  152.46 130.94 225 top
CV16  10U_0603_10V6M  [C_0603]  191.24 159.91 135 bottom
CV17  10P_0402_50V8D  [C_0402]  144 131.37 90 bottom
CV18  10P_0402_50V8D  [C_0402]  144 130.3 270 bottom
CV19  10U_0603_6.3V6M  [C_0603]  153.22 125.73 135 top
CV20  1U_0402_6.3V4Z  [C_0402]  158.43 129.79 315 top
CV21  0.1U_0402_10V6K  [C_0402]  157.92 129.03 315 top
CV26  1U_0402_6.3V4Z  [C_0402]  157.03 125.73 135 top
CV27  10U_0603_6.3V6M  [C_0603]  156.52 124.84 225 top
CV28  0.68U_0402_10V  [C_0402]  155.25 131.44 225 top
CV29  0.68U_0402_10V  [C_0402]  156.52 131.32 315 top
CV30  10U_0603_6.3V6M  [C_0603]  159.19 125.98 315 top
CV33  1U_0402_6.3V4Z  [C_0402]  160.08 127.89 315 top
CV34  0.1U_0402_10V6K  [C_0402]  159.44 127.25 315 top
CV35  0.1U_0402_10V6K  [C_0402]  158.24 126.93 135 top
CV38  10U_0603_6.3V6M  [C_0603]  145.97 131.71 135 top
CV39  0.1U_0402_10V6K  [C_0402]  149.66 131.95 45 top
CV40  2.2U_0402_6.3V6M  [C_0402]  166.55 135.25 315 top
CV41  2.2U_0402_6.3V6M  [C_0402]  162.24 143.51 135 top
CV42  2.2U_0402_6.3V6M  [C_0402]  162.11 140.72 225 top
CV43  10U_0603_6.3V6M  [C_0603]  191.24 159.91 135 top
CV44  10U_0603_6.3V6M  [C_0603]  168.09 166.96 45 top
CV45  10U_0603_6.3V6M  [C_0603]  167.37 166.23 225 top
CV46  1U_0402_6.3V4Z  [C_0402]  146.87 132.59 135 top
CV47  2.2U_0402_6.3V6M  [C_0402]  178.81 135.01 270 top
CV48  2.2U_0402_6.3V6M  [C_0402]  161.4 141.25 135 top
CV49  0.1U_0402_10V6K  [C_0402]  162.87 140.21 225 top
CV50  0.1U_0402_10V6K  [C_0402]  179.7 135.01 270 top
CV51  0.1U_0402_10V6K  [C_0402]  165.92 134.62 315 top
CV52  0.1U_0402_10V6K  [C_0402]  168.71 134.87 225 top
CV53  0.1U_0402_10V6K  [C_0402]  163.51 139.57 225 top
CV54  10U_0603_6.3V6M  [C_0603]  157.41 144.02 225 top
CV55  10U_0603_6.3V6M  [C_0603]  156.53 144.87 225 top
CV56  1U_0402_6.3V4Z  [C_0402]  159.82 140.97 225 top
CV57  1U_0402_6.3V4Z  [C_0402]  158.17 138.43 135 top
CV58  1U_0402_6.3V4Z  [C_0402]  157.92 142.88 225 top
CV59  1U_0402_6.3V4Z  [C_0402]  158.93 139.32 135 top
CV60  1U_0402_6.3V4Z  [C_0402]  159.19 141.6 225 top
CV61  10U_0603_6.3V6M  [C_0603]  150.81 128.4 135 top
CV62  1U_0402_6.3V4Z  [C_0402]  156.65 133.73 135 top
CV63  0.1U_0402_10V6K  [C_0402]  157.28 134.49 135 top
CV64  1U_0402_6.3V4Z  [C_0402]  150.42 126.62 135 bottom
CV65  1U_0402_6.3V4Z  [C_0402]  158.43 131.57 135 top
CV66  1U_0402_6.3V4Z  [C_0402]  158.55 132.71 135 top
CV67  10U_0603_6.3V6M  [C_0603]  167.32 125.98 225 top
CV68  10U_0603_6.3V6M  [C_0603]  161.3 133.58 225 top
CV69  10U_0603_6.3V6M  [C_0603]  163.63 121.16 0 top
CV70  10U_0603_6.3V6M  [C_0603]  168.38 125.17 45 top
CV71  1U_0402_6.3V4Z  [C_0402]  162.24 132.44 315 top
CV72  1U_0402_6.3V4Z  [C_0402]  164.27 134.49 135 top
CV73  1U_0402_6.3V4Z  [C_0402]  166.68 129.41 45 top
CV74  1U_0402_6.3V4Z  [C_0402]  164.01 131.42 315 top
CV75  1U_0402_6.3V4Z  [C_0402]  165.61 133.15 225 top
CV76  1U_0402_6.3V4Z  [C_0402]  162.62 128.4 45 top
CV77  1U_0402_6.3V4Z  [C_0402]  161.55 121.26 180 top
CV78  1U_0402_6.3V4Z  [C_0402]  161.54 137.16 225 top
CV79  1U_0402_6.3V4Z  [C_0402]  163.63 136.4 315 top
CV80  1U_0402_6.3V4Z  [C_0402]  150.55 136.91 135 top
CV81  10U_0603_6.3V6M  [C_0603]  171.5 131.7 315 top
CV82  1U_0402_6.3V4Z  [C_0402]  170.36 131.32 225 top
CV84  10U_0603_6.3V6M  [C_0603]  177.98 130.43 225 top
CV85  1U_0402_6.3V4Z  [C_0402]  176.84 130.81 225 top
CV86  0.1U_0402_10V6K  [C_0402]  176.21 131.44 225 top
CV87  1U_0402_6.3V4Z  [C_0402]  165.28 137.29 225 top
CV88  10U_0603_6.3V6M  [C_0603]  160.86 129.26 45 top
CV89  1U_0402_6.3V4Z  [C_0402]  163.51 138.3 45 top
CV90  1U_0402_6.3V4Z  [C_0402]  162.87 137.16 135 top
CV91  10U_0603_6.3V6M  [C_0603]  179.25 131.32 315 top
CV92  1U_0402_6.3V4Z  [C_0402]  176.96 131.94 45 top
CV93  0.1U_0402_10V6K  [C_0402]  174.43 133.48 45 top
CV94  1U_0402_6.3V4Z  [C_0402]  153.12 145.77 135 bottom
CV95  1U_0402_6.3V4Z  [C_0402]  153.72 146.44 135 bottom
CV96  120P_0402_50V8J  [C_0402]  182.81 127 270 top
CV97  68P_0402_50V8J  [C_0402]  180.78 126.11 180 top
CV98  0.1U_0402_16V4Z  [C_0402]  175.7 129.41 135 top
CV99  0.1U_0402_16V4Z  [C_0402]  172.4 129.03 45 top
CV100  1U_0402_6.3V4Z  [C_0402]  163.63 130.56 315 top
CV101  1U_0402_6.3V4Z  [C_0402]  164.88 133.65 225 top
CV102  1U_0402_6.3V4Z  [C_0402]  160.18 130.07 45 top
CV103  1U_0402_6.3V4Z  [C_0402]  162.49 133.73 45 top
CV104  1U_0402_6.3V4Z  [C_0402]  164.45 127.7 315 top
CV105  1U_0402_6.3V4Z  [C_0402]  162.16 136.56 225 top
CV106  1U_0402_6.3V4Z  [C_0402]  158.68 134.19 315 top
CV107  1U_0402_6.3V4Z  [C_0402]  161.6 123.95 180 top
CV108  1U_0402_6.3V4Z  [C_0402]  163.56 122.43 0 top
CV109  1U_0402_6.3V4Z  [C_0402]  163.56 123.44 0 top
CV110  1U_0402_6.3V4Z  [C_0402]  161.55 122.17 180 top
CV111  1U_0402_6.3V4Z  [C_0402]  160.69 138.02 45 top
CV112  1U_0402_6.3V4Z  [C_0402]  168.03 132.94 135 top
CV113  1U_0402_6.3V4Z  [C_0402]  162.05 127.69 135 top
CV114  1U_0402_6.3V4Z  [C_0402]  165.16 129.03 315 top
CV115  1U_0402_6.3V4Z  [C_0402]  161.73 134.49 135 top
CV116  1U_0402_6.3V4Z  [C_0402]  159.82 135.13 45 top
CV117  1U_0402_6.3V4Z  [C_0402]  161.63 131.8 315 top
CV118  1U_0402_6.3V4Z  [C_0402]  165.39 131.29 315 top
CV119  1U_0402_6.3V4Z  [C_0402]  161.55 123.06 180 top
CV120  1U_0402_6.3V4Z  [C_0402]  157.36 137.59 135 top
CV121  1U_0402_6.3V4Z  [C_0402]  158.55 142.24 225 top
CV122  10U_0603_6.3V6M  [C_0603]  154.6 140.73 135 top
CV123  10U_0603_6.3V6M  [C_0603]  149.66 125.73 135 bottom
CV124  0.1U_0402_10V6K  [C_0402]  169.98 132.33 225 top
CV131  1U_0402_6.3V6K  [C_0402]  167.18 165.67 45 bottom
CV133  1U_0402_6.3V6K  [C_0402]  173.35 171.9 225 bottom
CV143  0.1U_0201_10V6K  [C_0201]  182.98 154.42 45 bottom
CV151  0.1U_0201_10V6K  [C_0201]  181.46 152.89 45 bottom
CV170  1U_0402_6.3V6K  [C_0402]  189.42 144.09 225 bottom
CV171  1U_0402_6.3V6K  [C_0402]  157.2 146.5 45 top
CV174  0.01U_0402_16V7K  [C_0402]  161.6 142.88 135 top
CV175  0.01U_0402_16V7K  [C_0402]  165.69 135.79 225 top
CV176  0.01U_0402_16V7K  [C_0402]  170.11 133.48 135 top
CV177  0.01U_0402_16V7K  [C_0402]  171.25 134.49 135 top
CV178  0.01U_0402_16V7K  [C_0402]  167.7 135.64 135 top
CV179  0.01U_0402_16V7K  [C_0402]  147.5 133.22 135 top
CV180  1U_0402_6.3V4Z  [C_0402]  156.15 141.99 225 top
CV181  1U_0402_6.3V4Z  [C_0402]  154.23 142.63 315 top
CV182  1U_0402_6.3V6K  [C_0402]  176.01 174.62 45 top
CV183  1U_0402_6.3V6K  [C_0402]  194.74 149.28 45 top
CV184  1U_0402_6.3V6K  [C_0402]  187.95 142.49 45 top
CV185  1U_0402_6.3V6K  [C_0402]  189.22 143.76 45 top
CV186  0.1U_0201_10V6K  [C_0201]  176.7 158.48 45 bottom
CV187  0.1U_0201_10V6K  [C_0201]  178.51 160.29 225 bottom
CV188  1U_0402_6.3V6K  [C_0402]  185.41 142.63 315 top
CV196  1U_0402_6.3V6K  [C_0402]  177.85 172.98 315 top
CV198  1U_0402_6.3V6K  [C_0402]  196.01 150.74 45 bottom
CV208  1U_0402_6.3V6K  [C_0402]  177.85 172.98 315 bottom
CV210  1U_0402_6.3V6K  [C_0402]  192.59 147.26 225 bottom
CV211  1U_0402_6.3V6K  [C_0402]  190.42 145.09 45 bottom
CV212  1U_0402_6.3V6K  [C_0402]  196.91 153.85 135 bottom
CV220  0.1U_0402_25V6  [C_0402]  195.31 149.99 315 bottom
CV224  0.01UF_0402_25V7K  [C_0402]  193.44 146.73 135 top
CV227  0.1U_0402_25V6  [C_0402]  192.14 146.75 315 top
CV304  0.22U_0402_16V7K  [C_0402]  150.88 143.57 135 bottom
CV305  0.22U_0402_16V7K  [C_0402]  147.07 142.3 135 bottom
CV306  0.22U_0402_16V7K  [C_0402]  147.32 139.76 135 bottom
CV307  0.22U_0402_16V7K  [C_0402]  148.84 141.41 135 bottom
CV308  0.22U_0402_16V7K  [C_0402]  146.43 141.66 135 bottom
CV309  0.22U_0402_16V7K  [C_0402]  149.48 142.04 135 bottom
CV310  .1U_0402_16V7K  [C_0402]  160.22 58.62 270 bottom
CV311  .1U_0402_16V7K  [C_0402]  161.11 58.62 270 bottom
CV312  0.22U_0402_16V7K  [C_0402]  146.68 139.12 135 bottom
CV313  0.22U_0402_16V7K  [C_0402]  150.24 142.93 135 bottom
CV327  0.1U_0402_25V6  [C_0402]  173.93 172.71 135 top
CV393  0.01UF_0402_25V7K  [C_0402]  171.32 171.4 315 top
CV394  10U_0603_10V6M  [C_0603]  198.48 152.89 225 bottom
CV395  0.1U_0201_10V6K  [C_0201]  196.72 153.92 135 top
CV396  1U_0402_6.3V6K  [C_0402]  165.6 164.14 45 bottom
CV397  0.1U_0201_10V6K  [C_0201]  170.25 168.8 225 top
CV398  10U_0603_10V6M  [C_0603]  196.16 150.51 45 top
CV399  0.1U_0402_25V6  [C_0402]  169.82 168.29 135 bottom
CV400  0.1U_0201_10V6K  [C_0201]  167.2 161.02 135 top
CV401  0.1U_0201_10V6K  [C_0201]  165.6 164.91 315 top
CV402  10U_0603_10V6M  [C_0603]  174.06 172.8 45 bottom
CV403  10U_0603_6.3V6M  [C_0603]  157.87 135.79 45 top
CVT90  0.1U_0402_10V7K  [C_0402]  168.2 129.41 45 top
CZ23  470P_0402_50V7K  [C_0402]  45.14 16.71 270 top
CZ30  10P_0402_50V8J  [C_0402]  60.71 78.49 180 top
CZ31  10P_0402_50V8J  [C_0402]  60.71 80.26 180 top
CZ34  0.1U_0402_10V7K  [C_0402]  184.14 70.73 90 bottom
CZ44  0.1U_0402_10V7K  [C_0402]  47.17 16.71 270 top
CZ45  470P_0402_50V7K  [C_0402]  46.28 16.71 270 top
CZ50  0.1U_0402_10V7K  [C_0402]  44.25 16.71 270 top
CZ70  470P_0402_50V7K  [C_0402]  130.63 109.47 180 top
CZ78  0.1U_0402_10V7K  [C_0402]  131.54 107.32 0 top
CZ82  0.1U_0402_10V7K  [C_0402]  134.85 116.13 90 top
CZ86  0.1U_0402_10V7K  [C_0402]  140.24 114.9 0 top
CZ87  1U_0402_6.3V6K  [C_0402]  140.25 113.28 0 top
CZ1701  0.1U_0402_25V6  [C_0402]  133.01 110.93 0 top
CZ1702  0.1U_0402_10V7K  [C_0402]  140.24 115.79 0 top
CZ1703  0.1U_0402_10V7K  [C_0402]  135.49 109.72 90 top
D2501  -  [BAS40C_SOT23-3]  29.94 11.56 270 top
D2502  -  [RB551V-30_SOD323-2]  185.66 31.42 180 top
D2601  RB551V30-GP  [LRB551V-30T1G_SOD323-2]  99.38 141.95 0 bottom
D2701  -  [BAT54C-7-F_SOT23-3]  179.38 30.8 90 bottom
D3801  -  [RB551V-30_SOD323-2]  56.69 76.07 0 top
D5201  -  [BAT54C-7-F_SOT23-3]  75.62 156.82 180 bottom
D5202  -  [BAT54C-7-F_SOT23-3]  60.54 164.24 270 top
D5203  -  [RB551V-30_SOD323-2]  102.48 153.11 90 bottom
D5401  -  [BAW56W_SOT323-3]  40.99 79.69 270 bottom
D5501  -  [RB551V-30_SOD323-2]  31.33 70.45 0 top
D5503  -  [RB551V-30_SOD323-2]  177.48 41.72 180 bottom
DA6  -  [PESD5V0U2BT_SOT23-3]  98.42 160.95 180 bottom
DA13  AZ5125-02S.R7G_SOT23-3  [AZ5125-02SPR7G_SOT23-3]  84.49 5.65 270 top
DA14  AZ5125-02S.R7G_SOT23-3  [AZ5125-02SPR7G_SOT23-3]  84.49 9.65 270 top
DB1  ACES_51522-01001-001  [ACES_51522-01001-001_10P]  158.3 48.96 180 bottom
DE8  AZ5125-01H.R7G_SOD523-2  [AZ5125-01HPR7G_SOD523-2]  173.03 68.35 90 top
DZ3  -  [RB751S40T1G_SOD523-2]  149.22 63.94 180 top
DZ4  -  [RB751S40T1G_SOD523-2]  157.79 56.45 270 bottom
DZ5  -  [RB751S40T1G_SOD523-2]  160.78 70.49 270 top
DZ1701  -  [RB751S40T1G_SOD523-2]  141.28 117.86 180 top
DZ1702  -  [RB751S40T1G_SOD523-2]  166.17 92.23 270 top
DZ1703  -  [RB751S40T1G_SOD523-2]  137.34 111.26 270 top
EC2601  .1U_0402_16V7K  [C_0402]  99.95 138.21 0 bottom
EC2602  10P_0402_50V8J  [C_0402]  96.93 141.06 180 bottom
EC2701  10P_0402_50V8J  [C_0402]  178.21 12.41 180 bottom
EC2703  0_0402_5%  [R0402_0OHM]  186.46 7.97 180 bottom
EC2704  0_0402_5%  [R0402_0OHM]  186.43 17.31 180 top
EC2705  0_0402_5%  [R0402_0OHM]  190.94 9.86 270 bottom
EC2706  0_0402_5%  [R0402_0OHM]  192.14 13.31 0 bottom
EC2707  0_0402_5%  [R0402_0OHM]  190.05 9.86 270 bottom
EC2708  .1U_0402_16V7K  [C_0402]  176.24 15.52 180 bottom
EC2709  .1U_0402_16V7K  [C_0402]  175.39 17.53 180 bottom
EC2901  1000P_0402_50V7K  [C_0402]  88.51 4.97 270 top
EC2902  1000P_0402_50V7K  [C_0402]  88.51 6.81 270 top
EC2903  1000P_0402_50V7K  [C_0402]  88.51 8.69 90 top
EC2904  1000P_0402_50V7K  [C_0402]  88.51 10.78 90 top
EC2905  100P_0402_50V8J  [C_0402]  186.49 22.05 270 top
EC2906  100P_0402_50V8J  [C_0402]  186.49 24.05 90 top
EC2907  100P_0402_50V8J  [C_0402]  187.38 27.99 90 top
EC2908  100P_0402_50V8J  [C_0402]  187.38 26.87 270 top
EC3101  10P_0402_50V8J  [C_0402]  39.7 171.09 90 bottom
EC3102  10P_0402_50V8J  [C_0402]  39.7 173.78 270 bottom
EC3103  10P_0402_50V8J  [C_0402]  39.7 174.64 90 bottom
EC3104  10P_0402_50V8J  [C_0402]  39.7 177.33 270 bottom
EC3105  10P_0402_50V8J  [C_0402]  39.19 171.09 90 top
EC3106  10P_0402_50V8J  [C_0402]  39.19 173.78 270 top
EC3107  10P_0402_50V8J  [C_0402]  39.19 174.64 90 top
EC3108  10P_0402_50V8J  [C_0402]  39.19 177.33 270 top
EC3201  10P_0402_50V8J  [C_0402]  21.58 18.82 270 bottom
EC3301  4.7P_0402_50V8C  [C_0402]  29.19 22.1 0 top
EC3302  4.7P_0402_50V8C  [C_0402]  28 9.66 270 top
EC3303  4.7P_0402_50V8C  [C_0402]  28.17 13.02 0 top
EC3304  4.7P_0402_50V8C  [C_0402]  28.17 14.29 0 top
EC3305  4.7P_0402_50V8C  [C_0402]  29.19 23.97 0 top
EC3306  4.7P_0402_50V8C  [C_0402]  29.19 21.08 0 top
EC3307  4.7P_0402_50V8C  [C_0402]  29.19 25.15 0 top
EC5206  6.8P_0402_50V8C  [C_0402]  94.04 157.18 270 bottom
EC5210  33P_0402_50V8J  [C_0402]  95.62 157.18 270 bottom
EC5801  33P_0402_50V8J  [C_0402]  173.15 70.87 0 bottom
EC5802  33P_0402_50V8J  [C_0402]  172.28 70.87 180 bottom
EC6101  1000P_0402_50V7K  [C_0402]  192.03 174.12 180 top
EC6102  220P_0402_50V7K  [C_0402]  32.77 3.78 0 top
EC6103  220P_0402_50V7K  [C_0402]  28.76 4.88 90 top
EC6105  .1U_0402_16V7K  [C_0402]  191.92 177.77 180 top
EC6207  .1U_0402_16V7K  [C_0402]  190.13 125.49 90 top
EC6208  .1U_0402_16V7K  [C_0402]  188.16 121.94 90 top
EC9701  0.1U_0402_25V6  [C_0402]  94.24 105.66 180 top
EC9702  1000P_0402_50V7K  [C_0402]  150.3 122.22 90 top
EC9703  0.1U_0402_25V6  [C_0402]  108.69 143.89 0 top
EC9705  0.1U_0402_25V6  [C_0402]  72.31 25.65 0 top
EC9706  0.1U_0402_25V6  [C_0402]  35.36 49.64 90 top
EC9708  1000P_0402_50V7K  [C_0402]  56.24 41.97 0 top
EC9709  1000P_0402_50V7K  [C_0402]  107.74 119.95 0 top
EC9710  1000P_0402_50V7K  [C_0402]  136.51 144.78 0 top
EC9712  0.1U_0402_25V6  [C_0402]  63.67 35.94 0 top
EC9713  0.1U_0402_25V6  [C_0402]  106.99 135.24 90 bottom
EC9714  1000P_0402_50V7K  [C_0402]  128.71 154.7 90 top
EC9715  1000P_0402_50V7K  [C_0402]  107.88 135.24 90 bottom
EC9716  1000P_0402_50V7K  [C_0402]  95.13 116.59 180 top
